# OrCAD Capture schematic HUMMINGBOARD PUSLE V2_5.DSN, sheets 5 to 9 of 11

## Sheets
5 13 HDMI: size B; title: HDMI
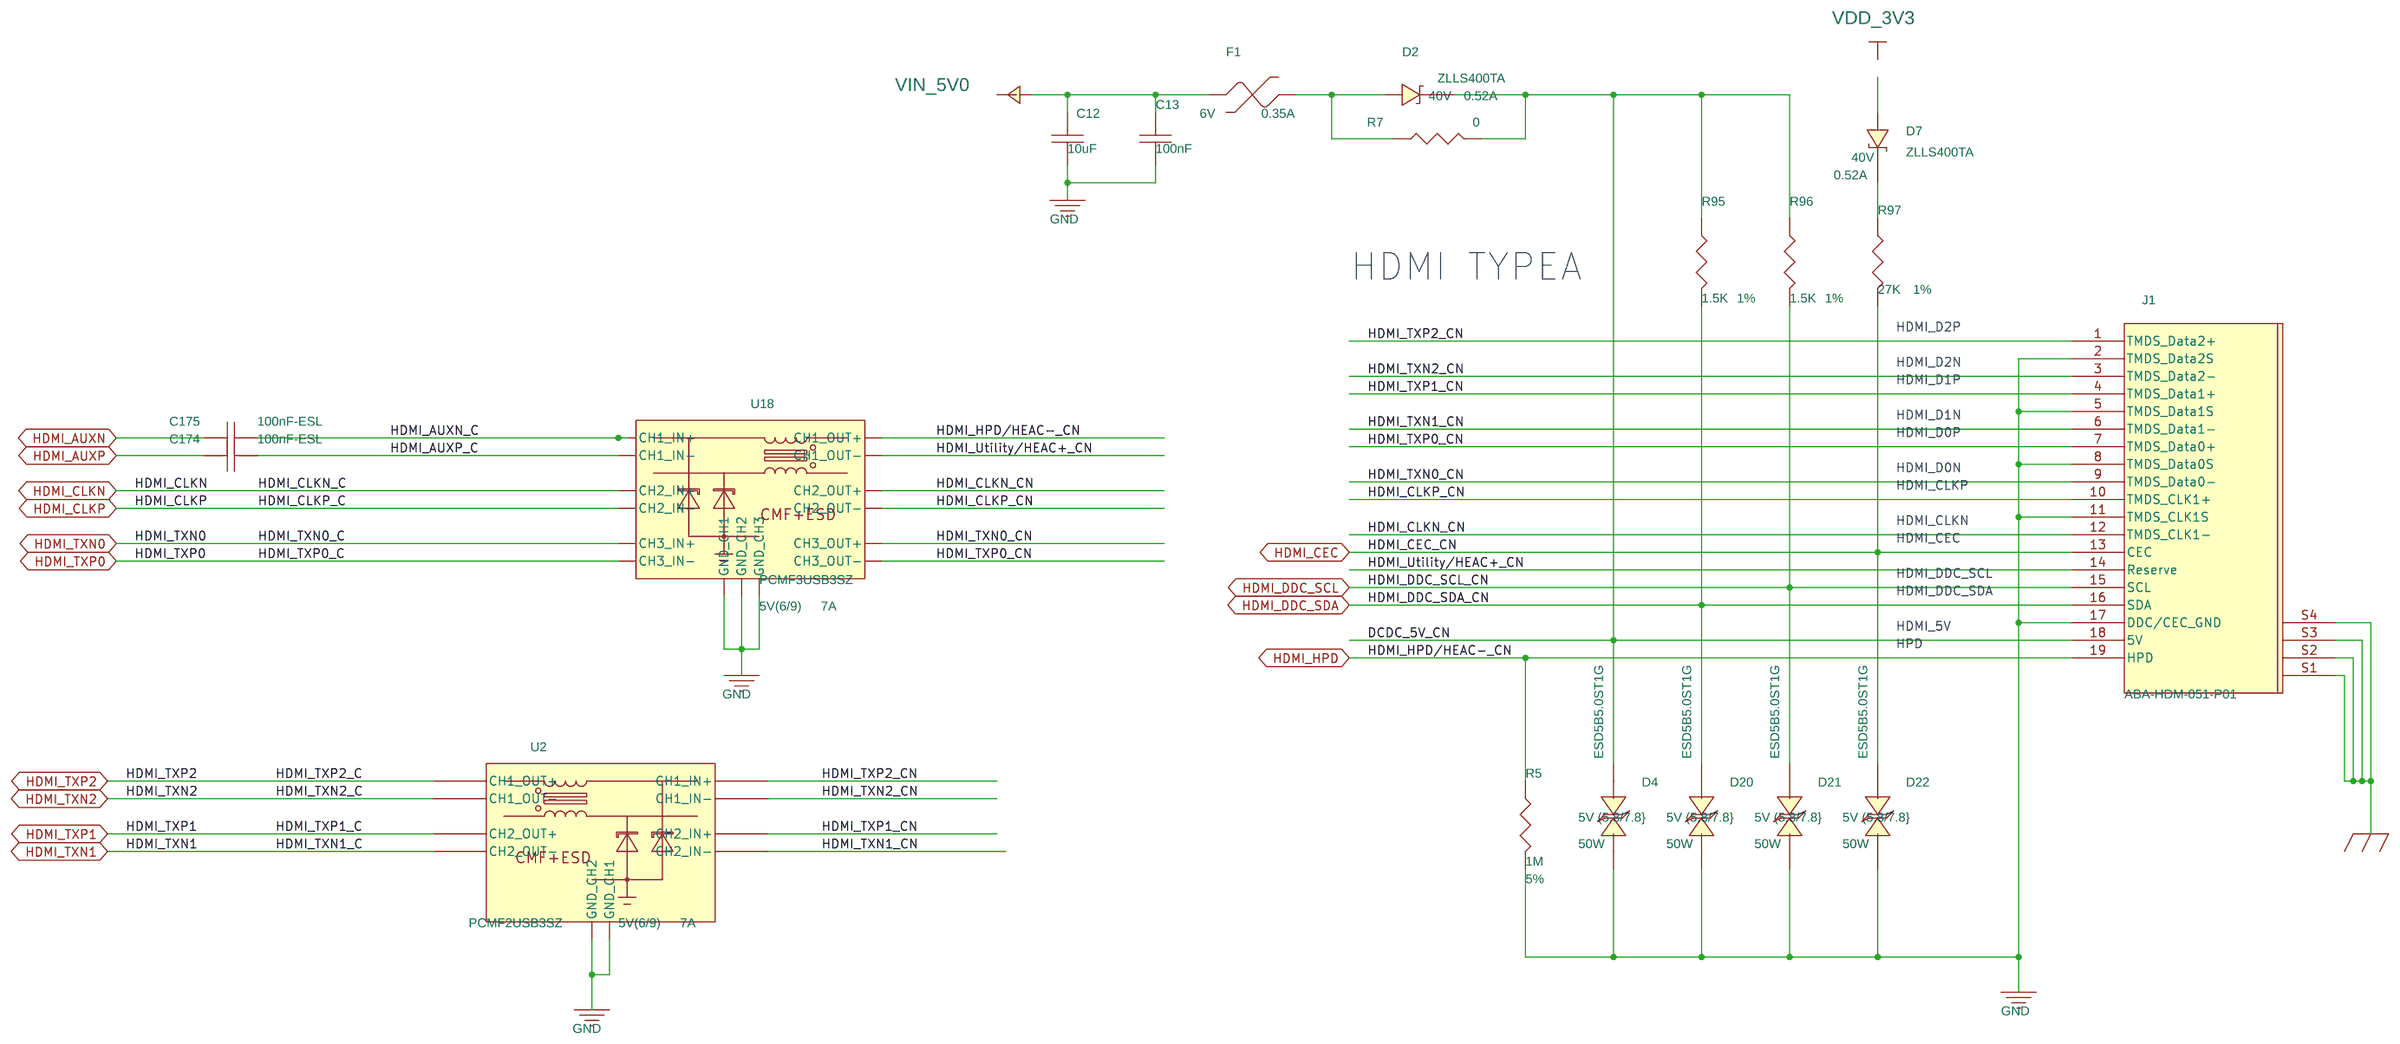
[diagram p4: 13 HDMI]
6 CODEC: size C; title: AUDIO
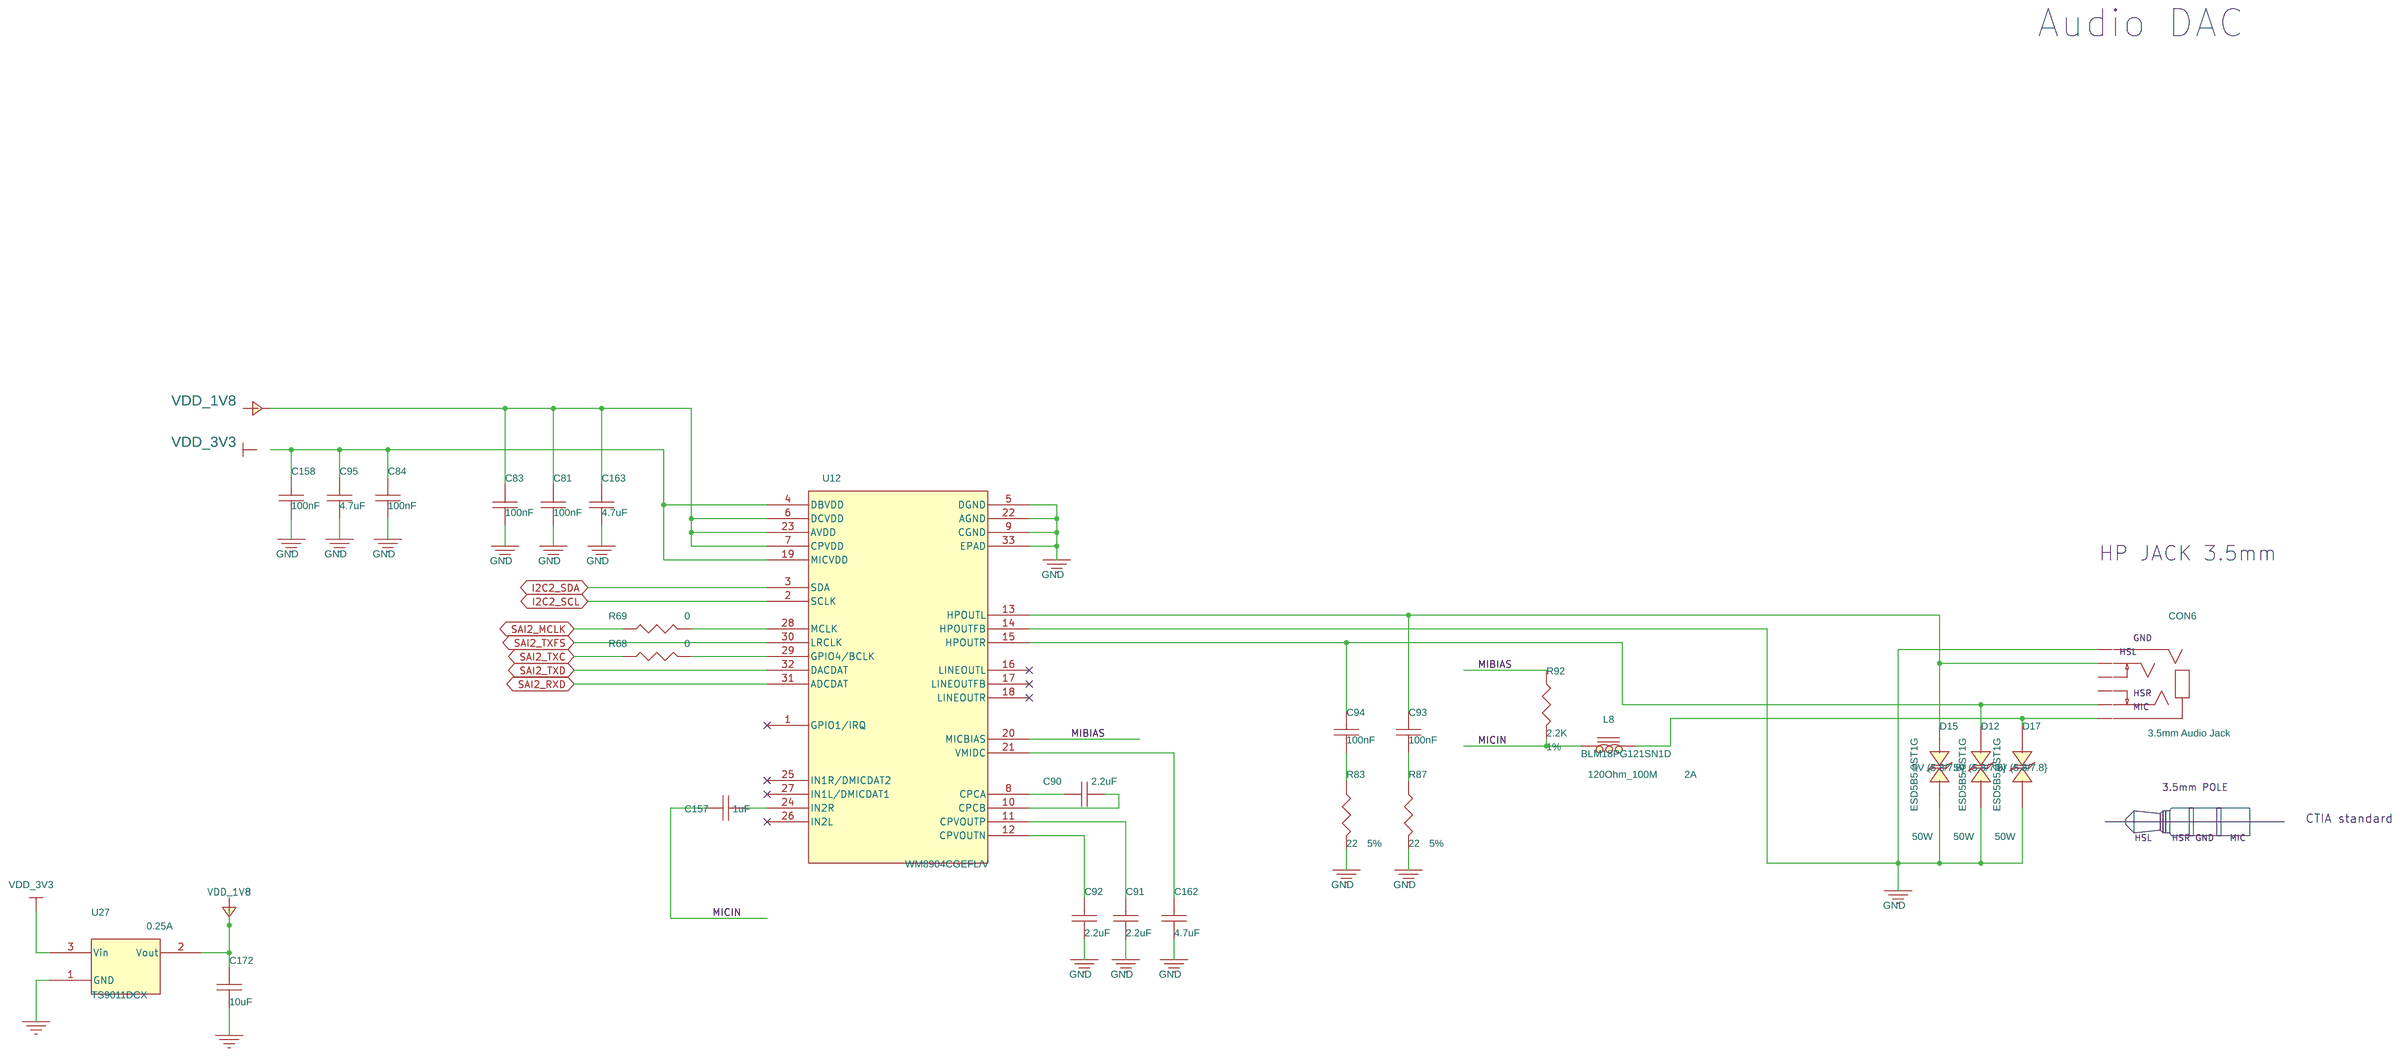
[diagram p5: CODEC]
7 Ethernet: size C; title: ETHERNET; rev: 2.4.0
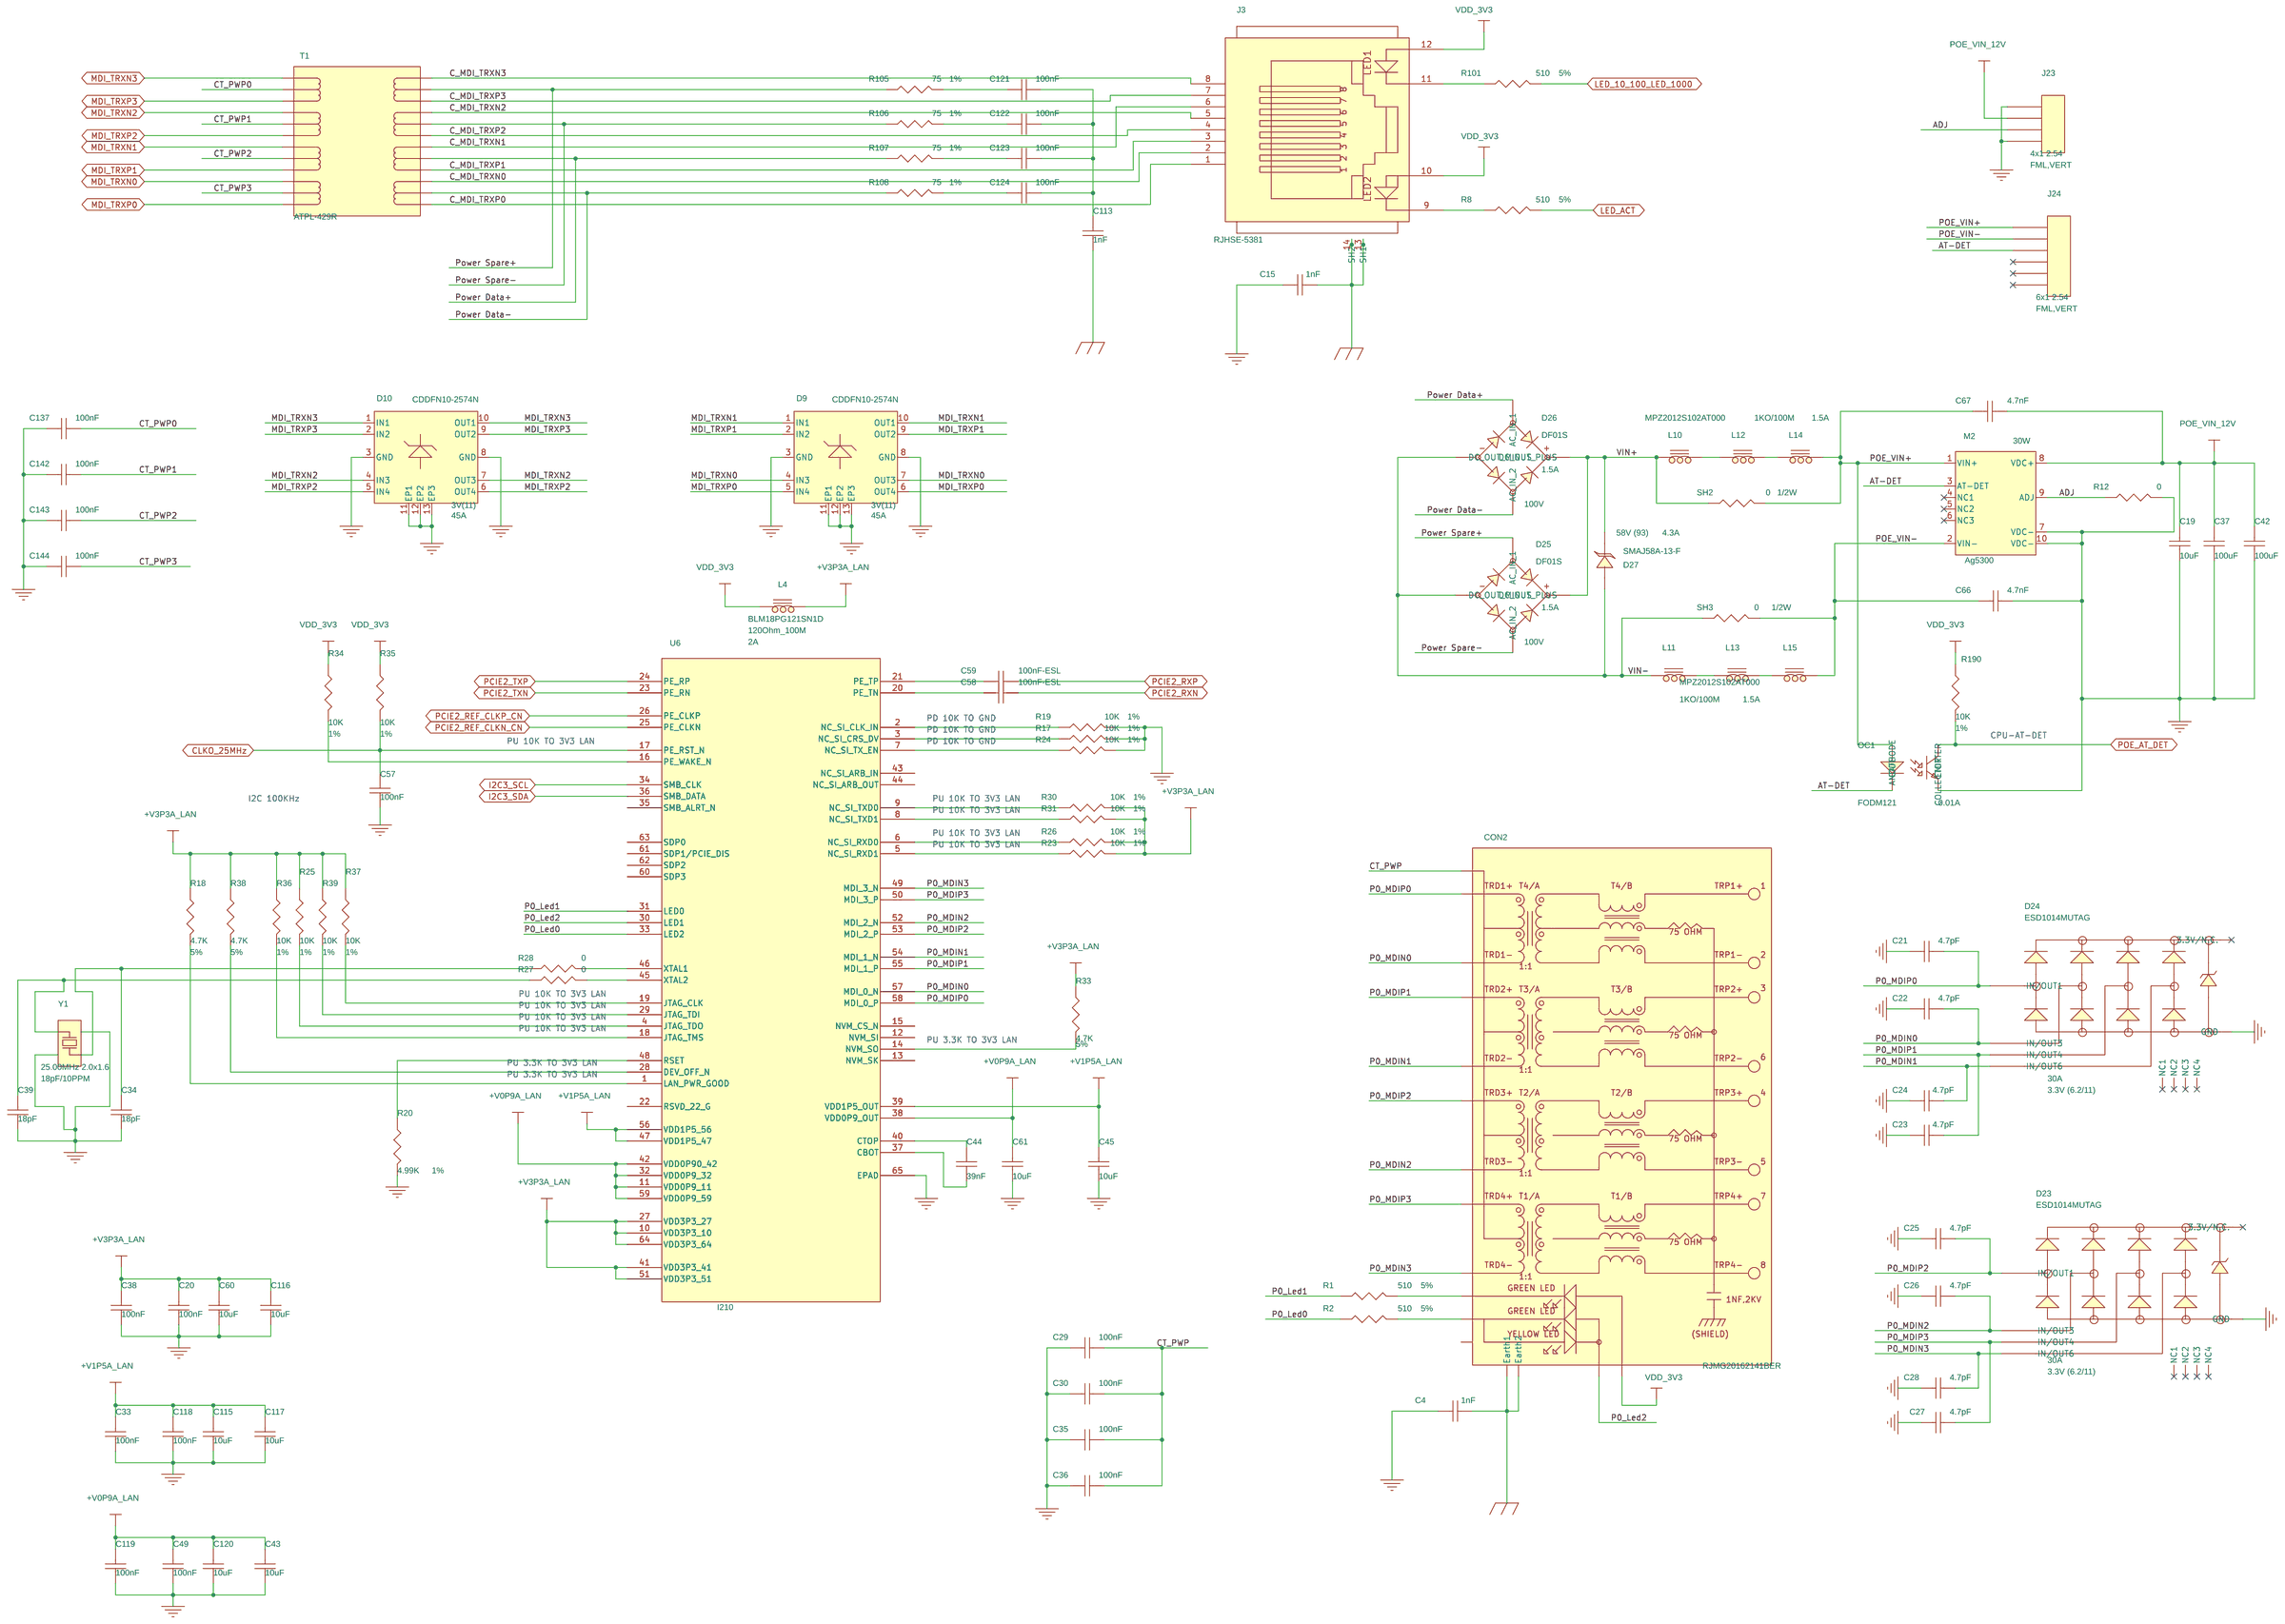
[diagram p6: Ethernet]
8 B-t-B Connectors: size C; title: B-T-B CONNECTORS; rev: 2.4.0
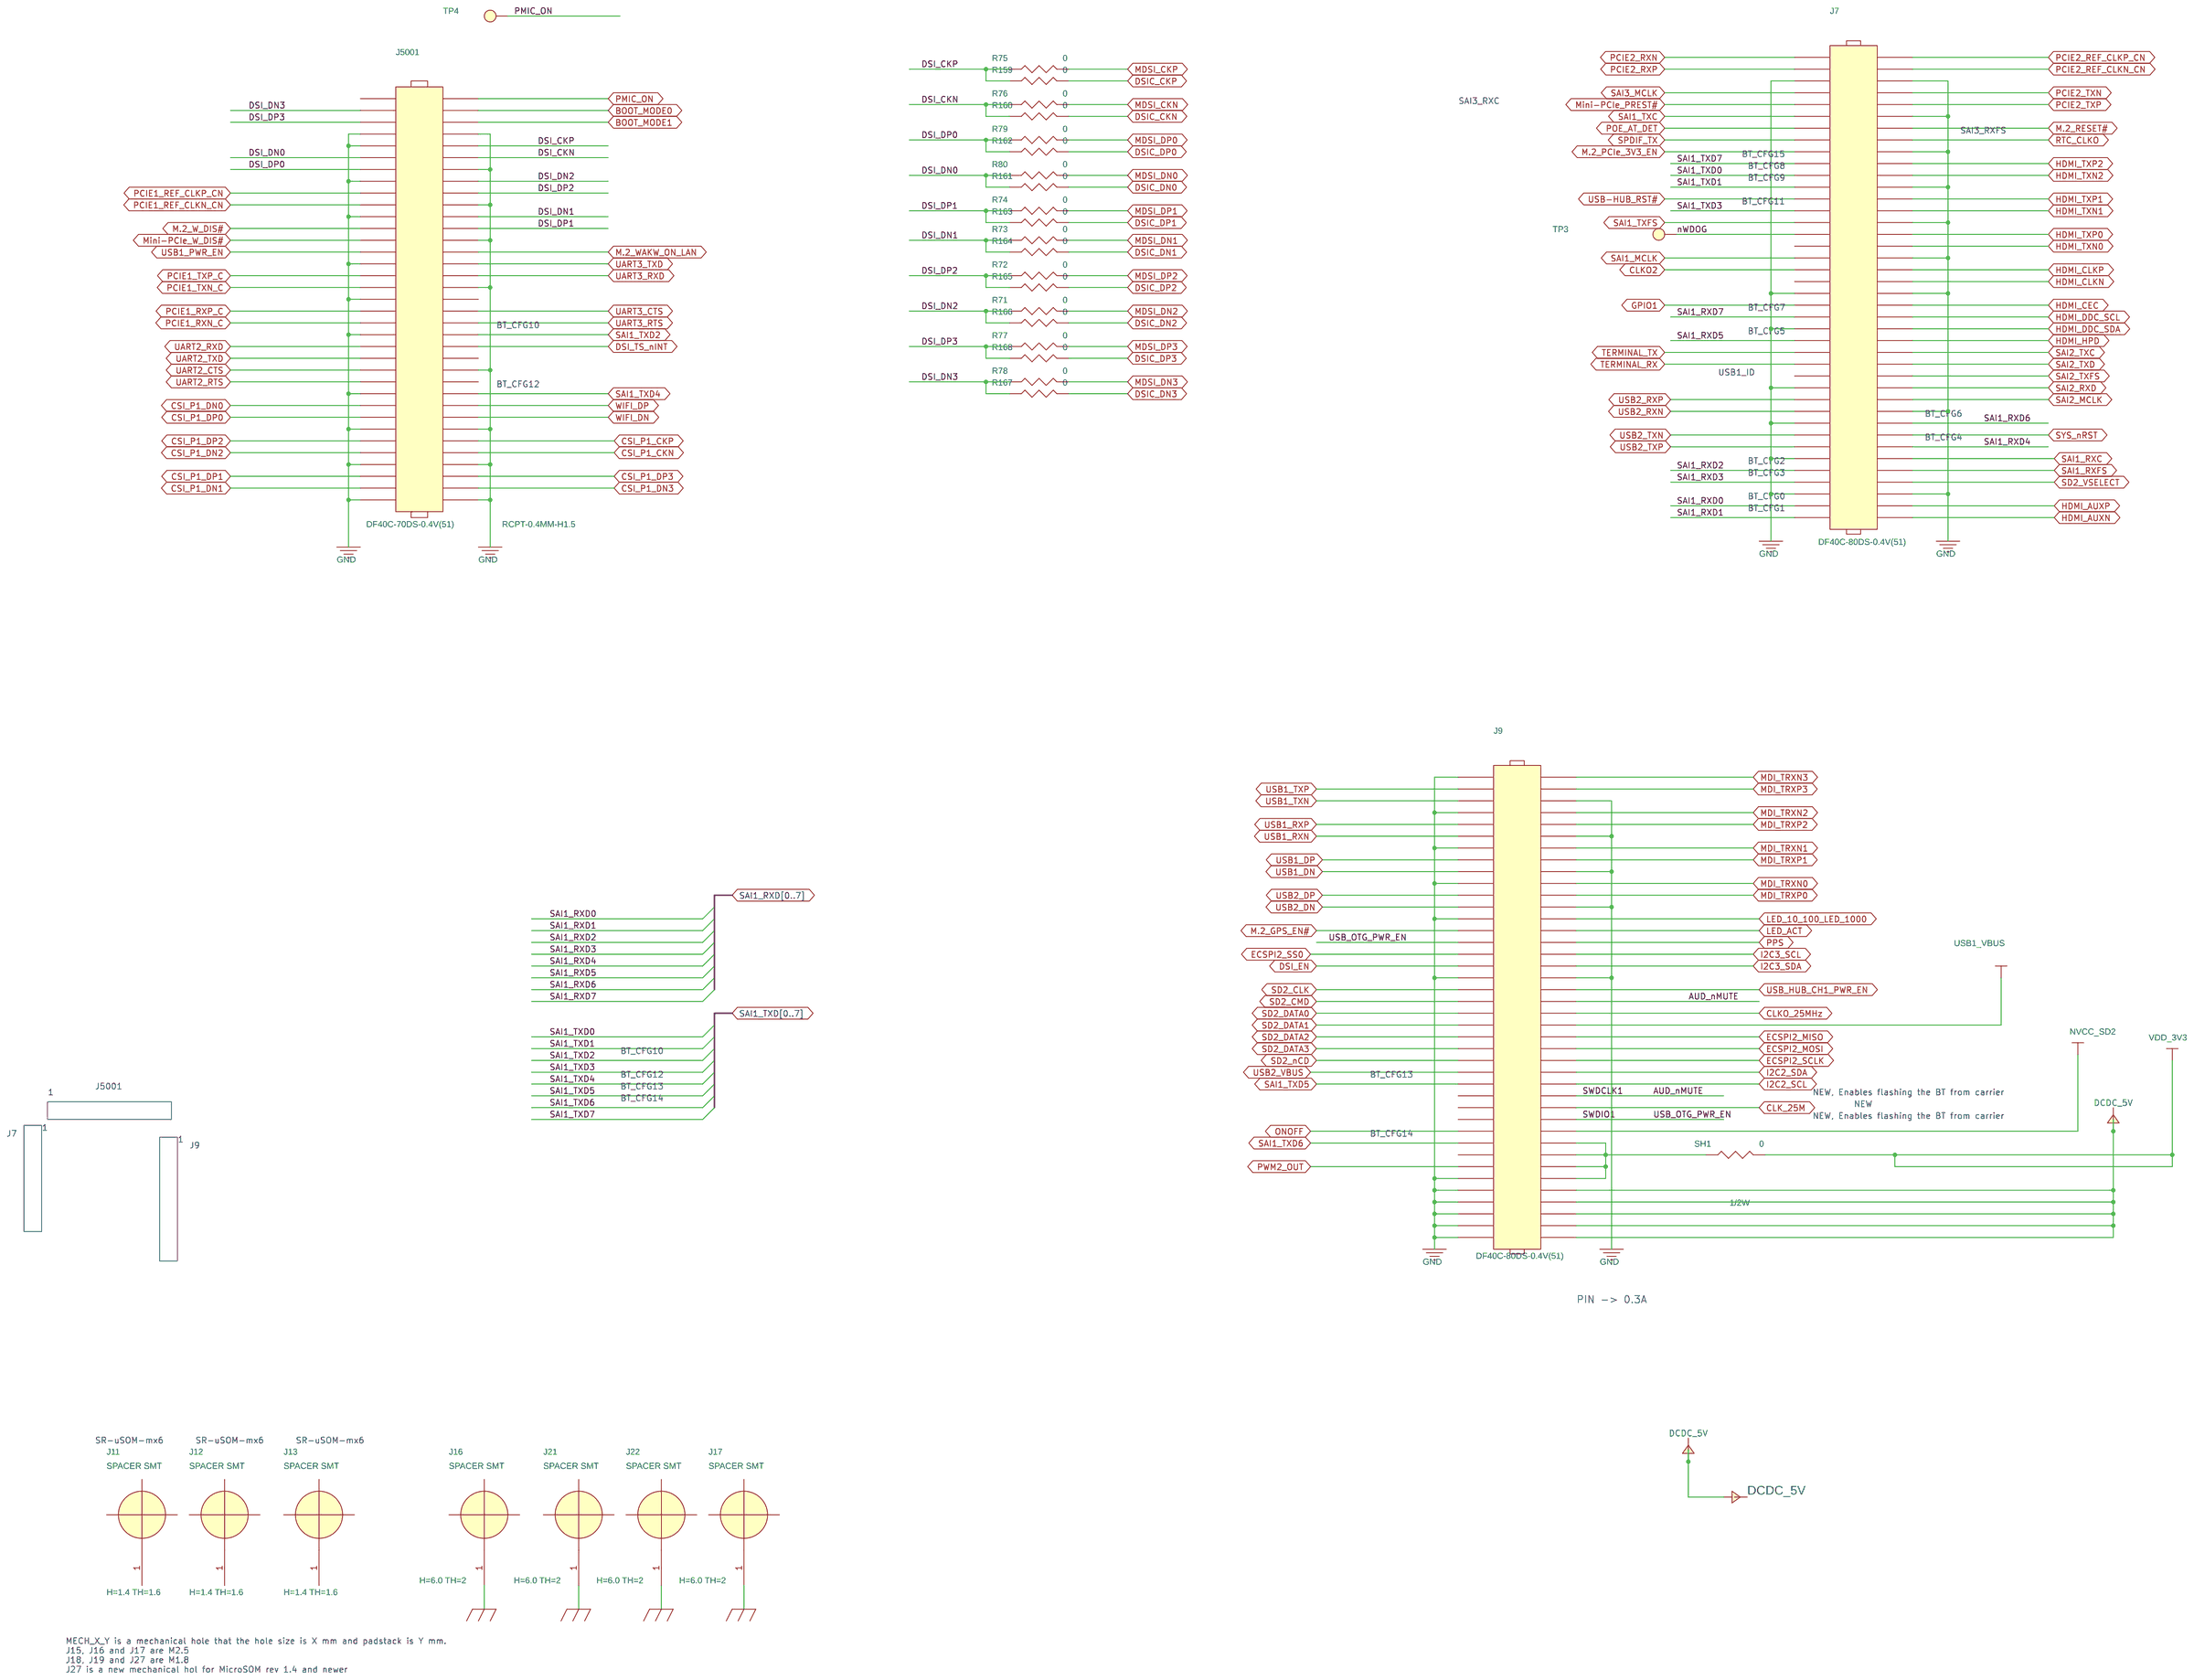
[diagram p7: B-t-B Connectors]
9 EXP CN: size C; title: BOOT, EXP; rev: 2.4.0
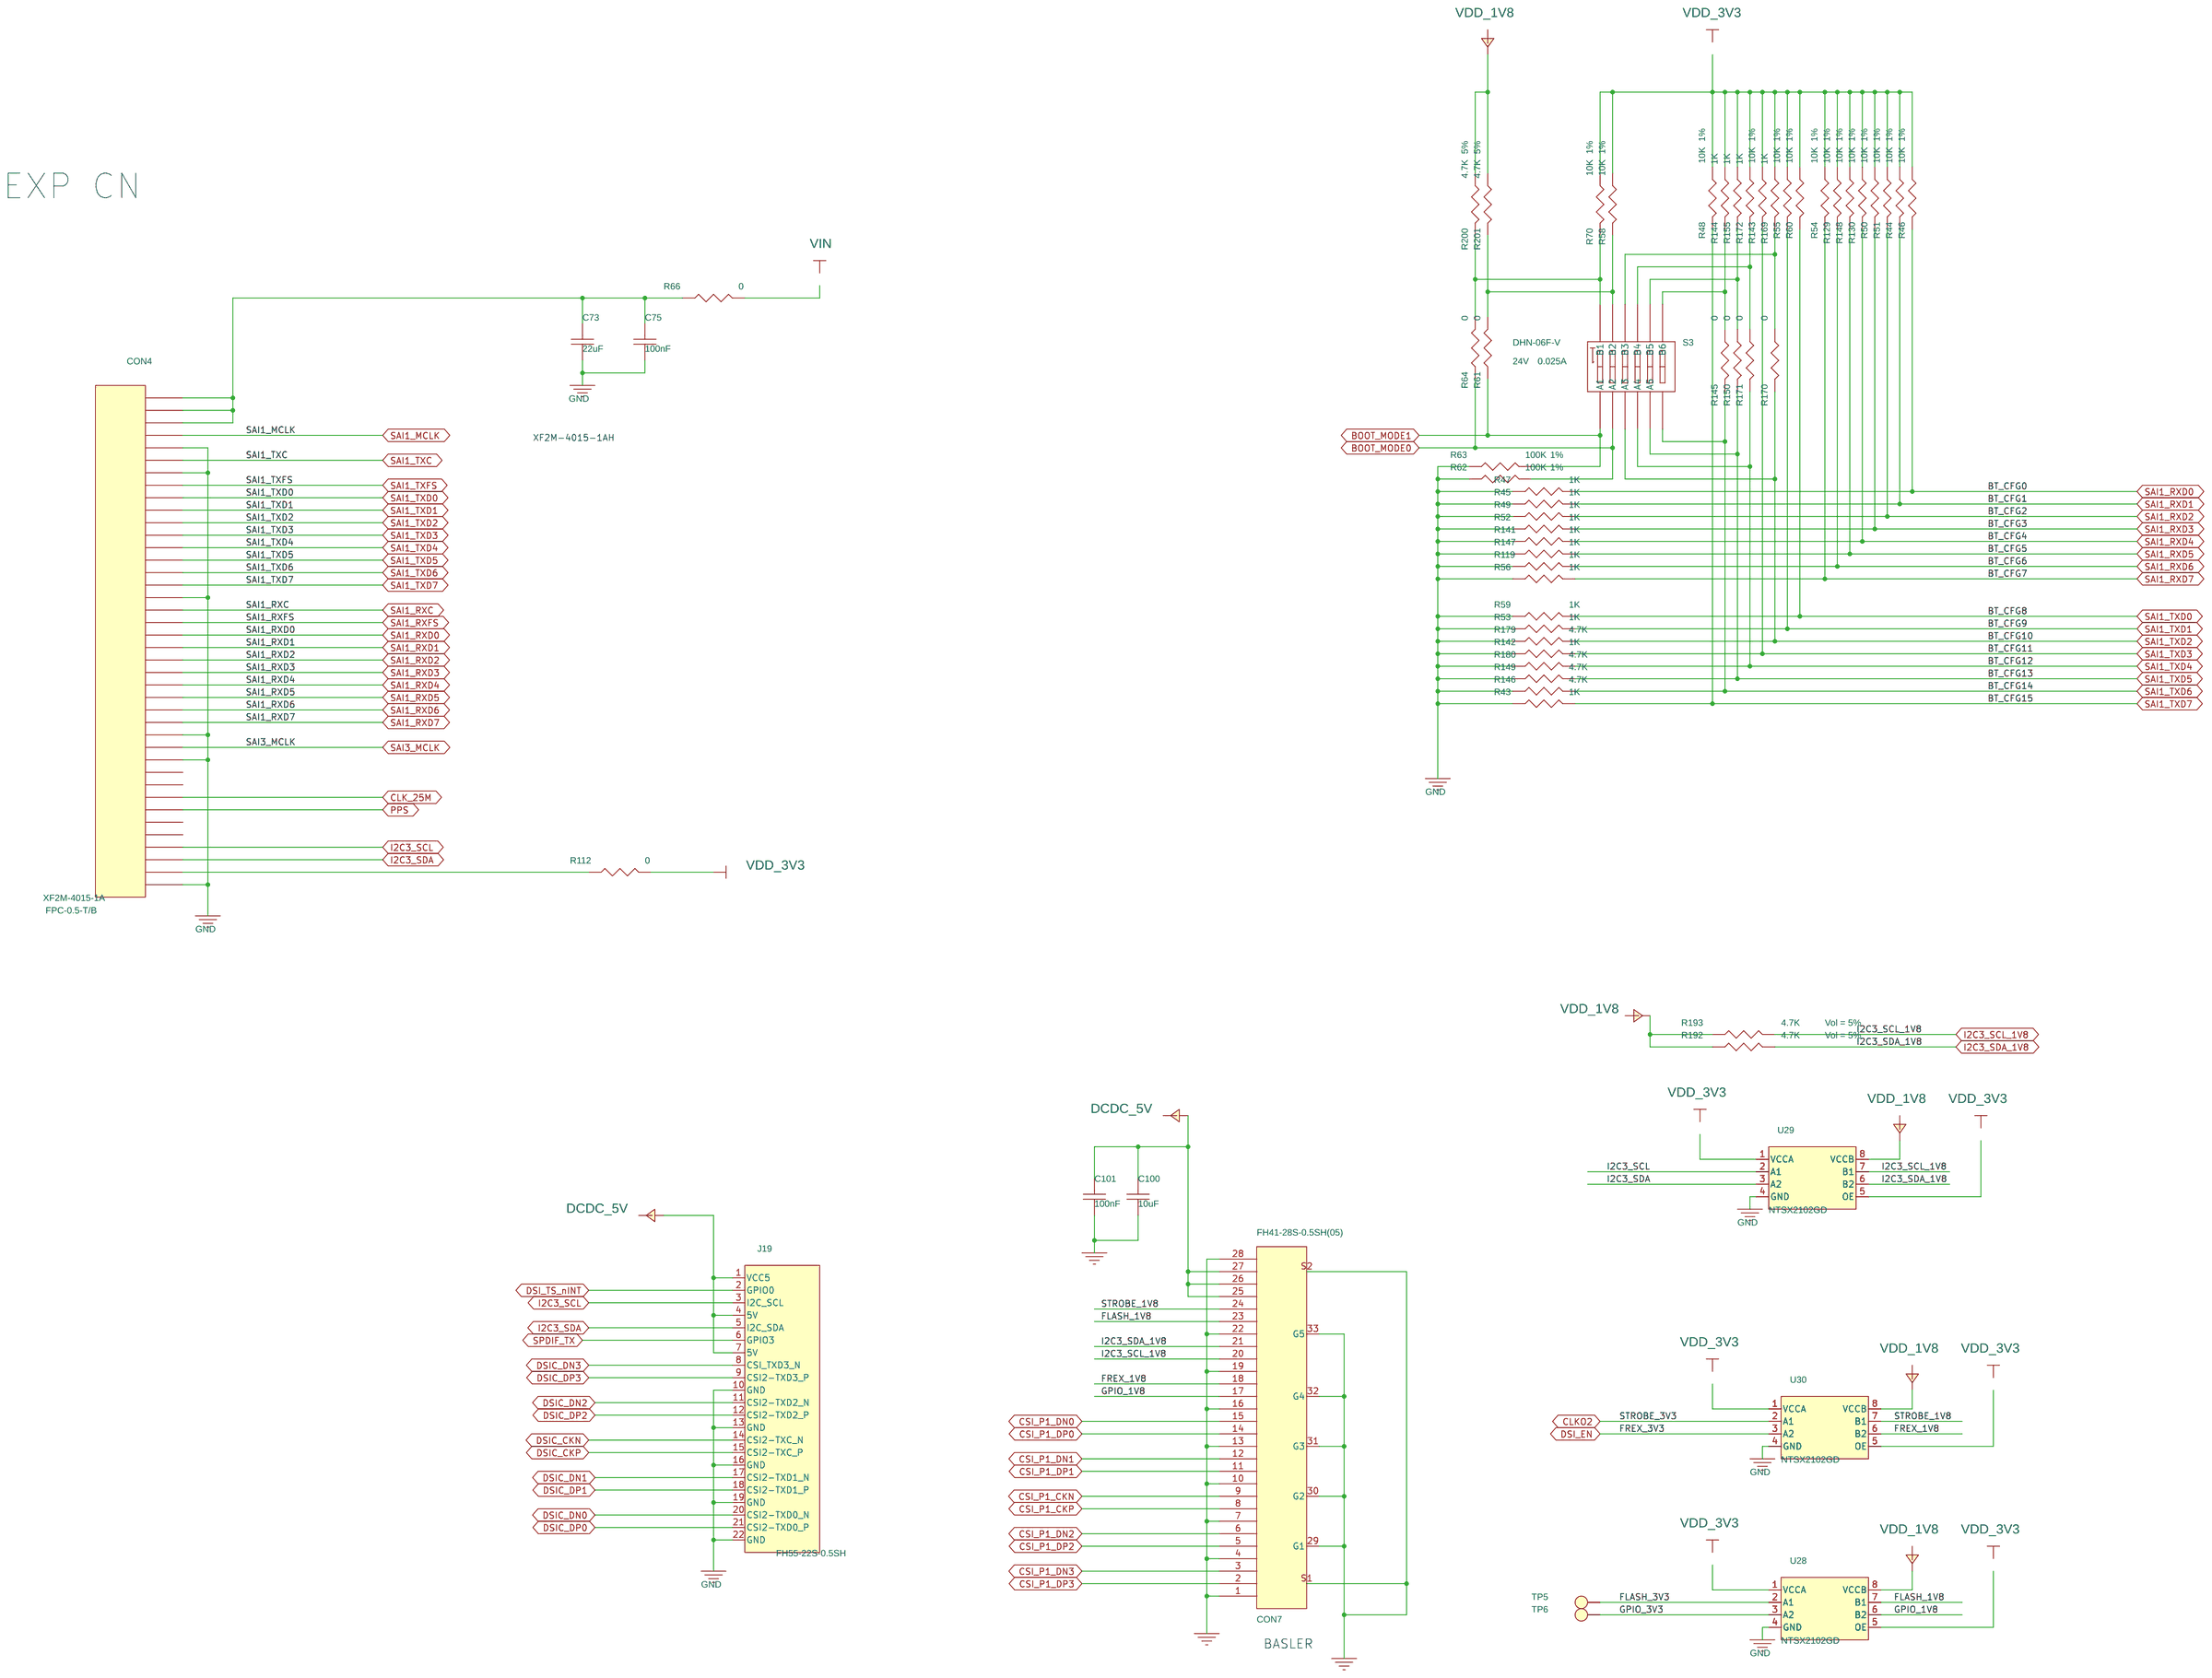
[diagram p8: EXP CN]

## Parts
sheet 13 HDMI
C12  10uF  [C0603]
C13  100nF  [C0402]
C174  100nF-ESL  [C0402]
C175  100nF-ESL  [C0402]
D2  ZLLS400TA  [ZLLS400TA]
D4  ESD5B5.0ST1G  [ESD5B5.0ST1G]
D7  ZLLS400TA  [ZLLS400TA]
D20  ESD5B5.0ST1G  [ESD5B5.0ST1G]
D21  ESD5B5.0ST1G  [ESD5B5.0ST1G]
D22  ESD5B5.0ST1G  [ESD5B5.0ST1G]
F1  6V  [PICOSMDC035S-2]
J1  ABA-HDM-051-P01  [ABA-HDM-051-P01]
R5  1M  [R0402]
R7  0  [R0402]
R95  1.5K  [R0402]
R96  1.5K  [R0402]
R97  27K  [R0402]
U2  PCMF2USB3SZ  [PCMF2USB3SZ]
U18  PCMF3USB3SZ  [PCMF3USB3SZ]
sheet B-t-B Connectors
J7  DF40C-80DS-0.4V(51)  [DF40C-80DS-0.4V(51)]
J9  DF40C-80DS-0.4V(51)  [DF40C-80DS-0.4V(51)]
J11  SPACER SMT
J12  SPACER SMT
J13  SPACER SMT
J16  SPACER SMT
J17  SPACER SMT
J21  SPACER SMT
J22  SPACER SMT
J5001  DF40C-70DS-0.4V(51)  [DF40C-70DS-0.4V(51)]
R71  0  [R0402]
R72  0  [R0402]
R73  0  [R0402]
R74  0  [R0402]
R75  0  [R0402]
R76  0  [R0402]
R77  0  [R0402]
R78  0  [R0402]
R79  0  [R0402]
R80  0  [R0402]
R159  0  [R0402]
R160  0  [R0402]
R161  0  [R0402]
R162  0  [R0402]
R163  0  [R0402]
R164  0  [R0402]
R165  0  [R0402]
R166  0  [R0402]
R167  0  [R0402]
R168  0  [R0402]
SH1  0  [R0603]
TP3  R 35
TP4  R 35
sheet CODEC
C81  100nF  [C0402]
C83  100nF  [C0402]
C84  100nF  [C0402]
C90  2.2uF  [C0402]
C91  2.2uF  [C0402]
C92  2.2uF  [C0402]
C93  100nF  [C0402]
C94  100nF  [C0402]
C95  4.7uF  [C0603]
C157  1uF  [C0402]
C158  100nF  [C0402]
C162  4.7uF  [C0603]
C163  4.7uF  [C0603]
C172  10uF  [C0603]
CON6  3.5mm Audio Jack  [PJ-3956-S124]
D12  ESD5B5.0ST1G  [ESD5B5.0ST1G]
D15  ESD5B5.0ST1G  [ESD5B5.0ST1G]
D17  ESD5B5.0ST1G  [ESD5B5.0ST1G]
L8  BLM18PG121SN1D  [BLM18PG121SN1D]
R68  0  [R0402]
R69  0  [R0402]
R83  22  [R0402]
R87  22  [R0402]
R92  2.2K  [R0402]
U12  WM8904CGEFL/V  [WM8904CGEFL/V]
U27  TS9011DCX  [TS9011DCX]
sheet Ethernet
C4  1nF  [C1206]
C15  1nF  [C1206]
C19  10uF  [C0805]
C20  100nF  [C0402]
C21  4.7pF  [C0402]
C22  4.7pF  [C0402]
C23  4.7pF  [C0402]
C24  4.7pF  [C0402]
C25  4.7pF  [C0402]
C26  4.7pF  [C0402]
C27  4.7pF  [C0402]
C28  4.7pF  [C0402]
C29  100nF  [C0402]
C30  100nF  [C0402]
C33  100nF  [C0402]
C34  18pF  [C0402]
C35  100nF  [C0402]
C36  100nF  [C0402]
C37  100uF  [C1210]
C38  100nF  [C0402]
C39  18pF  [C0402]
C42  100uF  [C1210]
C43  10uF  [C0603]
C44  39nF  [C0402]
C45  10uF  [C0603]
C49  100nF  [C0402]
C57  100nF  [C0402]
C58  100nF-ESL  [C0402]
C59  100nF-ESL  [C0402]
C60  10uF  [C0603]
C61  10uF  [C0603]
C66  4.7nF  [C1210]
C67  4.7nF  [C1210]
C113  1nF  [C1206]
C115  10uF  [C0603]
C116  10uF  [C0603]
C117  10uF  [C0603]
C118  100nF  [C0402]
C119  100nF  [C0402]
C120  10uF  [C0603]
C121  100nF  [C0402]
C122  100nF  [C0402]
C123  100nF  [C0402]
C124  100nF  [C0402]
C137  100nF  [C0402]
C142  100nF  [C0402]
C143  100nF  [C0402]
C144  100nF  [C0402]
CON2  RJMG20162141BER  [RJMG20162141BER]
D9  CDDFN10-2574N  [CDDFN10-2574N]
D10  CDDFN10-2574N  [CDDFN10-2574N]
D23  ESD1014MUTAG  [ESD1014MUTAG]
D24  ESD1014MUTAG  [ESD1014MUTAG]
D25  DF01S  [DF01S]
D26  DF01S  [DF01S]
D27  SMAJ58A-13-F  [SMAJ58A-13-F]
J3  RJHSE-5381  [RJHSE-5381]
J23  4x1 2.54  [SLW-104-01-G-S]
J24  6x1 2.54  [SLW-106-01-G-S]
L4  BLM18PG121SN1D  [BLM18PG121SN1D]
L10  MPZ2012S102AT000  [MPZ2012S102AT000]
L11  MPZ2012S102AT000  [MPZ2012S102AT000]
L12  MPZ2012S102AT000  [MPZ2012S102AT000]
L13  MPZ2012S102AT000  [MPZ2012S102AT000]
L14  MPZ2012S102AT000  [MPZ2012S102AT000]
L15  MPZ2012S102AT000  [MPZ2012S102AT000]
M2  Ag5300  [Ag5300]
OC1  FODM121  [FODM121]
R1  510  [R0402]
R2  510  [R0402]
R8  510  [R0402]
R12  0  [R0402]
R17  10K  [R0402]
R18  4.7K  [R0402]
R19  10K  [R0402]
R20  4.99K  [R0402]
R23  10K  [R0402]
R24  10K  [R0402]
R25  10K  [R0402]
R26  10K  [R0402]
R27  0  [R0402]
R28  0  [R0402]
R30  10K  [R0402]
R31  10K  [R0402]
R33  4.7K  [R0402]
R34  10K  [R0402]
R35  10K  [R0402]
R36  10K  [R0402]
R37  10K  [R0402]
R38  4.7K  [R0402]
R39  10K  [R0402]
R101  510  [R0402]
R105  75  [R0402]
R106  75  [R0402]
R107  75  [R0402]
R108  75  [R0402]
R190  10K  [R0402]
SH2  0  [R0603]
SH3  0  [R0603]
T1  ATPL-429R  [ATPL-429R]
U6  I210  [I210]
Y1  25.00MHz 2.0x1.6  [Q22FA1280026501]
sheet EXP CN
C73  22uF  [C0805]
C75  100nF  [C0402]
C100  10uF  [C0603]
C101  100nF  [C0402]
CON4  XF2M-4015-1A  [XF2M-4015-1A]
CON7  FH41-28S-0.5SH(05)  [FH41-28S-0.5SH(05)]
J19  FH55-22S-0.5SH  [FH55-22S-0.5SH]
R43  1K  [R0402]
R44  10K  [R0402]
R45  1K  [R0402]
R46  10K  [R0402]
R47  1K  [R0402]
R48  10K  [R0402]
R49  1K  [R0402]
R50  10K  [R0402]
R51  10K  [R0402]
R52  1K  [R0402]
R53  1K  [R0402]
R54  10K  [R0402]
R55  10K  [R0402]
R56  1K  [R0402]
R58  10K  [R0402]
R59  1K  [R0402]
R60  10K  [R0402]
R61  0  [R0402]
R62  100K  [R0402]
R63  100K  [R0402]
R64  0  [R0402]
R66  0  [R0402]
R70  10K  [R0402]
R112  0  [R0402]
R119  1K  [R0402]
R129  10K  [R0402]
R130  10K  [R0402]
R141  1K  [R0402]
R142  1K  [R0402]
R143  10K  [R0402]
R144  1K  [R0402]
R145  0  [R0402]
R146  4.7K  [R0402]
R147  1K  [R0402]
R148  10K  [R0402]
R149  4.7K  [R0402]
R150  0  [R0402]
R155  1K  [R0402]
R169  1K  [R0402]
R170  0  [R0402]
R171  0  [R0402]
R172  1K  [R0402]
R179  4.7K  [R0402]
R180  4.7K  [R0402]
R192  4.7K  [R0402]
R193  4.7K  [R0402]
R200  4.7K  [R0402]
R201  4.7K  [R0402]
S3  DHN-06F-V  [DHN-06F-V]
TP5  R 35
TP6  R 35
U28  NTSX2102GD  [NTSX2102GD]
U29  NTSX2102GD  [NTSX2102GD]
U30  NTSX2102GD  [NTSX2102GD]

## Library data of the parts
C12 C43 C45 C60 C61 C115-C117 C120 = CAP_NP1: CAP CER 10uF ±10% 16V X5R 0603; Category : Capacitors (Size: 0603); Digikey P/N: 490-10728-2-ND; Manufacturer: Murata Electronics North America; Part Num#: GRM188R61C106KAALD; Rating: 16V; SolidRun P/N: CA30014; Vol: 10%
C13 C20 C33 C38 C49 C57 C81 C83 C84 C93 C94 C118 C119 C158 = CAP_NP1: CAP CER 0.1uF ±10% 16V X7R 0402; Category : Capacitors (Size: 0402); Digikey P/N: 1276-1001-1-ND; Manufacturer: Samsung Electro-Mechanics; Part Num#: CL05B104KO5NNNC; Rating: 16V; SolidRun P/N: CA20013; Vol: 10%
C58 C59 C174 C175 = CAP_NP1: CAP CER 0.1uF ±10% 25V X7R 0402; Category : Capacitors (Size: 0402); Manufacturer: CAPAX; Part Num#: 0402X104K250SNT; Rating: 25V; SolidRun P/N: CA20090; Vol: 10%
D2 D7 = Diode-STK: DIODE SCHOTTKY 40V 520MA SOD323; Category: DI-Diode; Digikey P/N: ZLLS400TATR-ND; Manufacturer: Diodes Incorporated; Rating: 0.52A; SolidRun P/N: DI00234; Vol: 40V; Datasheet: https://www.diodes.com/assets/Datasheets/ZLLS400.pdf
D4 D12 D15 D17 D20-D22 = TVS-BI: TVS DIODE 5VWM SOD523 BI; Category : DI-TVS; Digikey P/N: ESD5B5.0ST1GOSTR-ND; Manufacturer: ON Semiconductor; Rating: 50W; SolidRun P/N: DI00242; Vol: 5V (5.8/7.8}; Datasheet: http://www.onsemi.com/pub/Collateral/ESD5B5.0ST1-D.PDF
F1 = FUSE_RESETTABLE: PTC RESET FUSE 6V 350MA 0805; Category : Fuse-PTC; Digikey P/N: PICOSMDC035S-2TR-ND; Manufacturer: Littelfuse Inc.; Rating: 0.35A; SolidRun P/N: FS00020; Datasheet: http://www.littelfuse.com/~/media/electronics/product_specifications/resettable_ptcs/littelfuse_ptc_picosmdc035s_2_product_specification.pdf.pdf
J1 = J-HDMI_connector: HDMI Connector; Category : CON-HDMI/DP; Manufacturer: LOTES; SolidRun P/N: CO00006; VOL: HDMI Connector
R5 = RES1: RES SMD 1M OHM 5% 1/16W 0402; Category : Resistors (Size: 0402); Digikey P/N: 311-1.0MJRCT-ND; Manufacturer: YAGEO; Part Num#: RC0402JR-071ML; Rating: 1/16W; SolidRun P/N: RE20416; Vol: 5%
R7 R12 R27 R28 R61 R64 R68 R69 R145 R150 R170 R171 = RES1: RES SMD 0 OHM JUMPER 1/16W 0402; Category : Resistors (Size: 0402); Digikey P/N: 311-0.0JRCT-ND; Manufacturer: YAGEO; Part Num#: RC0402JR-070RL; Rating: 1/16W; SolidRun P/N: RE20009
R95 R96 = RES1: RES SMD 1.5K OHM 1% 1/16W 0402; Category : Resistors (Size: 0402); Manufacturer: THYE MING; Part Num#: CR-02FL6---1K5; Rating: 1/16W; SolidRun P/N: RE20029; Vol: 1%
R97 = RES1: RES SMD 27K OHM 1% 1/16W 0402; Category : Resistors (Size: 0402); Digikey P/N: 311-27.0KLRCT-ND; Manufacturer: YAGEO; Part Num#: RC0402FR-0727KL; Rating: 1/16W; SolidRun P/N: RE20495; Vol: 1%
U2 = D-PCMF2USB3S: CMC 4LN SMD ESD USB 3.1, USB 2.0, HDMI 2.0, HDMI 1.4; Category : DI-TVS; Digikey P/N: 1727-2509-2-ND; Manufacturer: Nexperia USA Inc.; Rating: 7A; SolidRun P/N: DI00240; Vol: 5V(6/9); Datasheet: https://assets.nexperia.com/documents/data-sheet/PCMFXUSB3S_SER.pdf
U18 = D-PCMF3USB3S: CMC 6LN SMD ESD USB 3.1, USB 2.0, HDMI 2.0, HDMI 1.4; Category : DI-TVS; Digikey P/N: 1727-2510-2-ND; Manufacturer: Nexperia USA Inc.; Rating: 7A; SolidRun P/N: DI00239; Vol: 5V(6/9); Datasheet: https://assets.nexperia.com/documents/data-sheet/PCMFXUSB3S_SER.pdf
J7 J9 = J-DF40C-80DS-0.4V(51): CONN RCPT 80POS 0.4MM SMD GOLD Without reinforcing metal fitting 1.5mm; Category : CON-HEADER; Digikey P/N: H11633TR-ND; Manufacturer: Hirose Electric Co Ltd; SolidRun P/N: CO00017; VOL: RCPT-0.4MM-H1.5; Datasheet: https://www.hirose.com/product/download/?distributor=digikey&type=2d&lang=en&num=DF40C-80DS-0.4V(51)
J11-J13 = SPACER_SMT: SPACER H=1.4MM  TH=1.6MM - Used as imx6-uSOM spacer; Category : MECH-SPACER; Manufacturer: A-Link; Part Num#: N0143416A; SolidRun P/N: MCH0007; Vol: H=1.4 TH=1.6; Datasheet: http://www.alink.com.tw/smt%20fastener%20standard%20parts.html
J16 J17 J21 J22 = SPACER_SMT: 6mm PCB spacer to enclsoure (used in HummingBoard); Category : MECH-SPACER; Digikey P/N: 732-7103-2-ND; Manufacturer: Wurth Elektronik; Part Num#: WE 977-406-024-3R; SolidRun P/N: MCH0009; Vol: H=6.0 TH=2; Datasheet: http://katalog.we-online.de/em/datasheet/9774060243R.pdf
J5001 = J-DF40C-70DS-0.4V(51): CONN RCPT 70POS 0.4MM SMD GOLD Without reinforcing metal fitting 1.5 mm; Category : CON-HEADER; Digikey P/N: H11631TR-ND; Manufacturer: Hirose Electric Co Ltd; SolidRun P/N: CO00511; VOL: RCPT-0.4MM-H1.5; Datasheet: https://www.hirose.com/product/download/?distributor=digikey&type=2d&lang=en&num=DF40C-70DS-0.4V(51)
R71-R80 R159-R168 = RES1: RES SMD 0 OHM JUMPER 1/16W 0402; Category: Resistors (Size: 0402); Category : Resistors (Size: 0402); Digikey P/N: 311-0.0JRCT-ND; Manufacturer: YAGEO; Part Num#: RC0402JR-070RL; Rating: 1/16W; SolidRun P/N: RE20009
SH1-SH3 = RES1: RES SMD 0 OHM JUMPER 1/2W 0603; Category : Resistors (Size: 0603); Digikey P/N: 36-5110CT-ND; Manufacturer: Keystone Electronics; Part Num#: 5110; Rating: 1/2W; SolidRun P/N: RE30017
TP3-TP6 = T_POINT_R: TEST POINT MINIATURE SMT; Category : Test Point
C90-C92 = CAP_NP1: CAP CER 2.2uF ±20% 10V X5R 0402; Category : Capacitors (Size: 0402); Digikey P/N: 399-7375-1-ND; Manufacturer: KEMET; Part Num#: C0402C225M8PACTU; Rating: 10V; SolidRun P/N: CA20805; Vol: 20%
C95 C162 C163 = CAP_NP1: CAP CER 4.7uF ±10% 6.3V X5R; Category : Capacitors (Size: 0603); Digikey P/N: 1276-1045-2-ND; Manufacturer: Samsung Electro-Mechanics; Part Num#: CL10A475KQ8NNNC; Rating: 6.3V; SolidRun P/N: CA30003; Vol: 10%
C157 = CAP_NP1: CAP CER 1UF 10V X5R 0402; Category : Capacitors (Size: 0402); Digikey P/N: 1276-1076-1-ND; Manufacturer: Samsung Electro-Mechanics; Part Num#: CL05A105KP5NNNC; Rating: 10V; SolidRun P/N: CA20005; Vol: 10%
C172 = CAP_NP1: CAP CER 10uF ±10% 6.3V X5R 0603; Category : Capacitors (Size: 0603); Digikey P/N: 1276-1038-1-ND; Manufacturer: Samsung Electro-Mechanics; Part Num#: CL10A106KQ8NNNC; Rating: 6.3V; SolidRun P/N: CA30001; Vol: 10%
CON6 = J-PJ-3956-S124-AUDIO: 3.5mm Audio Jack with Microphone input and switch left and right; Category : CON-AUDIO; Manufacturer: Contact Technology; SolidRun P/N: CO00637
L4 L8 = Ferrite_Bead: Bead 120ohm, 100MHz, 2A; Category : COILS-FERRIT; Digikey P/N: 490-1037-2-ND; Manufacturer: Murata Electronics North America; Rating: 2A; SolidRun P/N: IN00003; Vol: 120Ohm_100M; Datasheet: https://www.murata.com/en-us/products/productdata/8796738650142/ENFA0003.pdf
R83 R87 = RES1: RES SMD 22 OHM 5% 1/16W 0402; Category : Resistors (Size: 0402); Digikey P/N: 311-22JRCT-ND; Manufacturer: YAGEO; Part Num#: RC0402JR-0722RL; Rating: 1/16W; SolidRun P/N: RE20021; Vol: 5%
R92 = RES1: RES SMD 2.2K OHM 1% 1/16W 0402; Category : Resistors (Size: 0402); Digikey P/N: 311-2.20KLRCT-ND; Manufacturer: YAGEO; Part Num#: RC0402FR-072K2L; Rating: 1/16W; SolidRun P/N: RE20204; Vol: 1%
U12 = IC-WM8904: IC CODEC STEREO ULP 32QFN; Category : IC-AUDIO; Digikey P/N: WM8904CGEFL/V-ND; Manufacturer: Cirrus Logic Inc; SolidRun P/N: IC01220; Datasheet: https://d3uzseaevmutz1.cloudfront.net/pubs/proDatasheet/WM8904_Rev4.0.pdf
U27 = IC-TS9011DCX: LDO - 1.8V output, 0.25A, 12V maximum in; Category : IC-PWR-LDO; Digikey P/N: TS9011DCXRFG-ND; Manufacturer: Taiwan Semiconductor Corporation; Rating: 0.25A; SolidRun P/N: IC00014; VOL: 1.8V; Datasheet: http://www.taiwansemi.com/products/datasheet/TS9011_H1608.pdf
C4 C15 C113 = CAP_NP1: CAP CER 1nF ±10% 1KV X7R 1206; Category : Capacitors (Size: 1206); Digikey P/N: 490-3494-2-ND; Manufacturer: Murata Electronics North America; Part Num#: GRM31BR73A102KW01L; Rating: 1KV; SolidRun P/N: CA50002; Vol: 10%
C19 = CAP_NP1: CAP CER 10uF ±10% 25V X5R 0805; Category : Capacitors (Size: 0805); Digikey P/N: 490-5523-1-ND; Manufacturer: Murata Electronics North America; Part Num#: GRM21BR61E106KA73L; Rating: 25V; SolidRun P/N: CA40005; Vol: 10%
C21-C28 = CAP_NP1: CAP CER 4.7pF ±0.05pF 50V C0G/NP0 0402; Category : Capacitors (Size: 0402); Digikey P/N: 311-1033-1-ND; Manufacturer: Murata Electronics North America; Part Num#: GJM1555C1H4R7WB01D; Rating: 50V; SolidRun P/N: CA20807; Vol: 1%
C29 C30 C35 C36 C121-C124 C137 C142-C144 = CAP_NP1: CAP CER 0.1uF ±10% 50V X7R 0402; Category : Capacitors (Size: 0402); Digikey P/N: 490-10700-1-ND; Manufacturer: Murata Electronics North America; Part Num#: GRM155R71H104KE14D; Rating: 50V; SolidRun P/N: CA20147; Vol: 10%
C34 C39 = CAP_NP1: CAP CER 18pF ±1% 50V C0G/NPO 0402; Category : Capacitors (Size: 0402); Digikey P/N: 311-1643-1-ND; Manufacturer: YAGEO; Part Num#: CC0402FRNPO9BN180; Rating: 50V; SolidRun P/N: CA20017; Vol: 1%
C37 C42 = CAP_NP1: CAP CER 100uF ±20% 16V X5R 1210; Category : Capacitors (Size: 1210); Digikey P/N: 311-2052-1-ND; Manufacturer: YAGEO; Part Num#: CC1210MKX5R7BB107; Rating: 16V; SolidRun P/N: CA60008; Vol: 20%
C44 = CAP_NP1: CAP CER 39nF ±10% 10V X5R 0402; Category : Capacitors (Size: 0402); Digikey P/N: 490-8252-1-ND; Manufacturer: Murata Electronics North America; Part Num#: GRM155R61A393KA01D; Rating: 10V; SolidRun P/N: CA20804; Vol: 10%
C66 C67 = CAP_NP1: CAP CER 4.7nF ±10% 2000V X7R 1210 .High Voltage; Category : Capacitors (Size: 1210); Digikey P/N: 399-7104-1-ND; Manufacturer: KEMET; Part Num#: C1210C472KGRACTU; Rating: 2KV; SolidRun P/N: CA60009; Vol: 10%
CON2 = J-RJMG20162141BER-FCI: CONN MAGJACK 1PORT 1000 BASE-T; Category : CON-ETH/RJ; Digikey P/N: RJMG20162141BER-ND; Manufacturer: Amphenol Commercial Products; SolidRun P/N: CO00673; VOL: MAGJACK; Datasheet: https://www.amphenolcanada.com/ProductSearch/Drawings/AC/RJMG20162141BER.PDF
D9 D10 = D-CDDFN10-2574N: TVS Diode Array, 4 Channel, Ipp=45A, Vclump=11V, 1.7pF@1MHz, 10-DFN (3x2), -55°C ~ 85°C (TA); Category: DI-TVS; Digikey P/N: CDDFN10-2574NCT-ND; Manufacturer: Bourns Inc.; Rating: 45A; SolidRun P/N: DI00271; Vol: 3V(11); Datasheet: https://www.bourns.com/docs/product-datasheets/cddfn10-2574n.pdf
D23 D24 = D-ESD1014: TVS DIODE 3.3VWM 11VC 10UDFN; Category : DI-TVS; Digikey P/N: ESD1014MUTAGOSTR-ND; Manufacturer: ON Semiconductor; Rating: 30A; SolidRun P/N: DI00238; Vol: 3.3V (6.2/11); Datasheet: http://www.onsemi.com/pub/Collateral/ESD1014-D.PDF
D25 D26 = D-DF01S-Bridge: IC RECT BRIDGE 100V 1.5A 4-SMD; Category : DI-Diode; Digikey P/N: DF01STR-ND; Manufacturer: ON Semiconductor; Rating: 1.5A; SolidRun P/N: DI00235; Vol: 100V; Datasheet: https://www.fairchildsemi.com/datasheets/DF/DF005S.pdf
D27 = TVS-UNI-OLD: TVS DIODE 58VWM 93.6VC SMA; Category : DI-TVS; Digikey P/N: SMAJ58A-13-FDITR-ND; Manufacturer: Diodes Incorporated; Rating: 4.3A; SolidRun P/N: DI00244; Vol: 58V (93); Datasheet: https://www.diodes.com/assets/Datasheets/ds19005.pdf
J3 = J-RJHSE538x: CONN MOD JACK 8P8C R/A SHIELDED; Category : CON-ETH/RJ; Digikey P/N: RJHSE-5381-ND; Manufacturer: Amphenol Commercial Products; SolidRun P/N: CO00654; VOL: JACK 8P8C R/A SHIELDED; Datasheet: https://www.amphenolcanada.com/ProductSearch/drawings/AC/RJHSE538X.pdf
J23 = J-HEADER-4x1: 4 Position Receptacle Connector  Through Hole; Digikey P/N: SAM1089-04-ND; Manufacturer: Samtec Inc.; SolidRun P/N: CO00780; Vol: FML,VERT; Datasheet: http://suddendocs.samtec.com/catalog_english/slw.pdf
J24 = J-HEADER-6x1: 6 Position Receptacle Connector  Through Hole; Digikey P/N: SAM1089-06-ND; Manufacturer: Samtec Inc.; SolidRun P/N: CO00781; Vol: FML,VERT; Datasheet: http://suddendocs.samtec.com/prints/slw-s.pdf
L10-L15 = Ferrite_Bead: 1 kOhms @ 100MHz 1 Power Line Ferrite Bead 0805 (2012 Metric) 1.5A 150mOhm; Category: COILS-FERRIT; Category : COILS-FERRIT; Digikey P/N: 445-5223-2-ND; Manufacturer: TDK Corporation; Rating: 1.5A; SolidRun P/N: IN00128; Vol: 1KO/100M; Datasheet: https://product.tdk.com/info/en/catalog/datasheets/beads_commercial_power_mpz2012_en.pdf
M2 = M-AG5300-POE: Module POE PD, IEEE802.3at, 30W, Vout=12V, 57x14mm; Category: IC-ETH-POE; Manufacturer: Silvertel; Rating: 30W; SolidRun P/N: IC01301; VOL: 802.3af/at PD; Datasheet: http://silvertel.com/images/datasheets/Ag5300-datasheet-smallest-30W-Power-Over-Ethernet-Plus-Module-PoEplusPD.pdf
OC1 = OPTC-DC-4P: Optoisolator Transistor Output 3750Vrms 1 Channel 4-Mini-Flat; Category: IC-INT-OPT; Digikey P/N: FODM121-ND; Manufacturer: ON Semiconductor; Rating: 0.01A; SolidRun P/N: IC01209; VOL: 1.4V; Datasheet: https://www.fairchildsemi.com/datasheets/FO/FODM121.pdf
R1 R2 R8 R101 = RES1: RES SMD 510 OHM 5% 1/16W 0402; Category : Resistors (Size: 0402); Digikey P/N: 311-510JRCT-ND; Manufacturer: YAGEO; Part Num#: RC0402JR-07510RL; Rating: 1/16W; SolidRun P/N: RE20022; Vol: 5%
R17 R19 R23-R26 R30 R31 R34-R37 R39 R44 R46 R48 R50 R51 R54 R55 R58 R60 R70 R129 R130 R143 R148 R190 = RES1: RES SMD 10K OHM 1% 1/16W 0402; Category : Resistors (Size: 0402); Digikey P/N: 311-10.0KLRCT-ND; Manufacturer: YAGEO; Part Num#: RC0402FR-0710KL; Rating: 1/16W; SolidRun P/N: RE20013; Vol: 1%
R18 R33 R38 R146 R149 R179 R180 R200 R201 = RES1: RES SMD 4.7K OHM 5% 1/16W 0402; Category : Resistors (Size: 0402); Digikey P/N: 311-4.7KJRCT-ND; Manufacturer: YAGEO; Part Num#: RC0402JR-074K7L; Rating: 1/16W; SolidRun P/N: RE20002; Vol: 5%
R20 = RES1: RES SMD 4.99K OHM 1% 1/16W 0402; Category : Resistors (Size: 0402); Digikey P/N: 311-4.99KLRCT-ND; Manufacturer: YAGEO; Part Num#: RC0402FR-074K99L; Rating: 1/16W; SolidRun P/N: RE20026; Vol: 1%
R105-R108 = RES1: RES SMD 75 OHM 1% 1/16W 0402; Category : Resistors (Size: 0402); Digikey P/N: 311-75.0LRCT-ND; Manufacturer: YAGEO; Part Num#: RC0402FR-0775RL; Rating: 1/16W; SolidRun P/N: RE20401; Vol: 1%
T1 = ATPL-429R: 1000 BASE –T SINGLE PORT PoE MAGNETICS MODULE SMT; # of Mfr: XXX; Category : IC-ETH-POE; Component Eng Status: XXX; Cost: XXX; Excess Inv: XXX; GG Footprint: XXX; IC Input capacitance: n/a; IC TH/smt package/size: N/A; IC family: analog; IC generic number: n/a; IC max Vcc/max input voltage: n/a; IC max output current: n/a; IC power dissipation: n/a; IC speed: n/a; Lead Time (Days): XXX; Leads pitch: N/A; Lifecycle Phase: Prototype; Manufacturer: AOEM; Manufacturer's Part Number: VP6014 LF; Max operating temp: +70; Min operating temp: 0; Mounting Tech: SMT; Number: LT-0548-S0N; Quantity in Stock: XXX; Reflow Soldering Comp: Yes; SolidRun P/N: IC00933; Used In Active Products: Yes; Wave Soldering Comp: No; height: 6; lead count: 24; notes: XXX; Datasheet: http://www.atechoem.com/ProdComSpec/ATPL-429R.pdf
U6 = IC-i210: Intel® Ethernet Controller I210; Category : IC-ETH; Manufacturer: INTEL; Part Num#: WGI210AT S LJXR/1115; SolidRun P/N: IC01191
Y1 = XTAL-4P: FA-128 25.000000MHz 18.0pF +/- 10ppm; Category : OC-CRYSTAL; Digikey P/N: FA-12825.0000MF15Y-C3-ND; Manufacturer: EPSON; Rating: 18pF/10PPM; SolidRun P/N: OC00026; Datasheet: https://support.epson.biz/td/api/doc_check.php?dl=brief_FA-128_en.pdf
C73 = CAP_NP1: CAP CER 22uF ±20% 35V X5R 0805 . Low ESL; Digikey P/N: 445-14428-1-ND; Manufacturer: TDK Corporation; Part Num#: C2012X5R1V226M125AC; Rating: 35V; SolidRun P/N: CA40013; Vol: 20%
C75 = CAP_NP1: CAP CER 0.1uF ±10% 50V X7R 0402; Digikey P/N: 490-10700-1-ND; Manufacturer: Murata Electronics North America; Part Num#: GRM155R71H104KE14D; Rating: 50V; SolidRun P/N: CA20147; Vol: 10%; Voltage: 50V
C100 = CAP_NP1: CAP CER 10uF ±10% 16V X5R 0603; Category: Capacitors (Size: 0603); Digikey P/N: 490-10728-2-ND; Manufacturer: Murata Electronics North America; Part Num#: GRM188R61C106KAALD; Rating: 16V; SolidRun P/N: CA30014; Vol: 10%
C101 = CAP_NP1: CAP CER 0.1uF ±10% 10V X7R 0402; Category: Capacitors (Size: 0402); Digikey P/N: 1276-1002-2-ND; Manufacturer: Samsung Electro-Mechanics; Part Num#: CL05B104KP5NNNC; Rating: 10V; SolidRun P/N: CA20001; Vol: 10%
CON4 = J-FPC40: 40 Position FPC Connector Contacts, Top and Bottom 0.020" (0.50mm) Surface Mount, Right Angle; Digikey P/N: OR729TR-ND; Manufacturer: Omron Electronics Inc-EMC Div; SolidRun P/N: CO00681; Vol: FPC-0.5-T/B; Datasheet: https://media.digikey.com/pdf/Data%20Sheets/Omron%20PDFs/XF2M.pdf
CON7 = J-FPC28-FH41: 28 Position FFC Connector Contacts, Bottom 0.020" (0.50mm) Surface Mount, Right Angle; Category: CON-FPC; Digikey P/N: HFY028TR-ND; Manufacturer: Hirose Electric Co Ltd; SolidRun P/N: CO00730; VOL: FPC-0.5-B; Datasheet: https://www.hirose.com/product/download/?distributor=digikey&type=2d&lang=en&num=FH41-28S-0.5SH(05)
J19 = J-FPC22-HS: FFC & FPC Connectors Bottom 0.5MM 22P HIGH SPEED TRANSMISSION FPC - AV CAMERA; Category : CON-FPC; Digikey P/N: FH55-22S-0.5SH-ND; Manufacturer: HIROSE; SolidRun P/N: CO00677; VOL: FPC-0.5-B-HS; Datasheet: https://www.hirose.com/product/en/products/FH55/FH55-22S-0.5SH/
R43 R45 R47 R49 R52 R53 R56 R59 R119 R141 R142 R144 R147 R155 R169 R172 = RES1: RES SMD 1K OHM 5% 1/16W 0402; Category : Resistors (Size: 0402); Digikey P/N: 311-1.0KJRCT-ND; Manufacturer: YAGEO; Part Num#: RC0402JR-071KL; Rating: 1/16W; SolidRun P/N: RE20010; Vol: 5%
R62 R63 = RES1: RES SMD 100K OHM 1% 1/16W 0402; Category : Resistors (Size: 0402); Digikey P/N: 311-100KLRCT-ND; Manufacturer: YAGEO; Part Num#: RC0402FR-07100KL; Rating: 1/16W; SolidRun P/N: RE20482; Vol: 1%
R66 R112 = RES1: RES SMD 0 OHM JUMPER 1/16W 0402; Digikey P/N: 311-0.0JRCT-ND; Manufacturer: YAGEO; Part Num#: RC0402JR-070RL; Rating: 1/16W; SolidRun P/N: RE20009
R192 R193 = RES1: RES SMD 4.7K OHM 5% 1/16W 0402; Category: Resistors (Size: 0402); Digikey P/N: 311-4.7KJRCT-ND; Manufacturer: YAGEO; Part Num#: RC0402JR-074K7L; Rating: 1/16W; SolidRun P/N: RE20002; Vol: 5%
S3 = SW-DIP-6_SM: DIP Switches/SIP Switches Half Pitch Dip switch 1.6mm height; Category: Switches-DIP; Manufacturer: DIPTRONICS MANUFACTURING; Rating: 0.025A; SolidRun P/N: SW00026; Vol: 24V; Datasheet: http://www.dip.com.tw/en/en-product-information/en-switch002/item/2377-dhnf
U28-U30 = IC-NTSX2102: Voltage Level Translator Bidirectional 1 Circuit 2 Channel 50Mbps 8-XSON, SOT996-2 (2x3); Category: IC-LOGIC; Digikey P/N: 568-12385-2-ND; Manufacturer: NXP USA Inc.; SolidRun P/N: IC01311; VOL: 1.65V-5.5V; Datasheet: https://www.nxp.com/docs/en/data-sheet/NTSX2102.pdf

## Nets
+V0P9A_LAN: C43.1 C49.1 C61.1 C119.1 C120.1 U6.11(VDD0P9) U6.32(VDD0P9) U6.38(VDD0P9_OUT) U6.42(VDD0P90) U6.59(VDD0P9)
+V1P5A_LAN: C33.1 C45.1 C115.1 C117.1 C118.1 U6.39(VDD1P5_OUT) U6.47(VDD1P5) U6.56(VDD1P5)
+V3P3A_LAN: C20.1 C38.1 C60.1 C116.1 L4.2 R18.1 R23.2 R25.1 R26.2 R30.2 R31.2 R33.1 R36.1 R37.1 R38.1 R39.1 U6.10(VDD3P3) U6.27(VDD3P3) U6.41(VDD3P3) U6.51(VDD3P3) U6.64(VDD3P3)
GND: C4.2 C12.2 C13.2 C15.2 C19.2 C20.2 C21.2 C22.2 C23.2 C24.2 C25.2 C26.2 C27.2 C28.2 C29.1 C30.1 C33.2 C34.2 C35.1 C36.1 C37.2 C38.2 C39.2 C42.2 C43.2 C45.2 C49.2 C57.2 C60.2 C61.2 C66.2 C73.2 C75.2 C81.2 C83.2 C84.2 C91.2 C92.2 C95.2 C100.2 C101.2 C115.2 C116.2 C117.2 C118.2 C119.2 C120.2 C137.1 C142.1 C143.1 C144.1 C158.2 C162.2 C163.2 C172.2 CON4.5 CON4.7 CON4.17 CON4.28 CON4.30 CON4.40 CON6.2 CON7.1 CON7.4 CON7.7 CON7.10 CON7.13 CON7.16 CON7.19 CON7.22 CON7.28 CON7.29(G1) CON7.30(G2) CON7.31(G3) CON7.32(G4) CON7.33(G5) CON7.S1 CON7.S2 D4.1 D9.3(GND) D9.8(GND) D9.11(EP1) D9.12(EP2) D9.13(EP3) D10.3(GND) D10.8(GND) D10.11(EP1) D10.12(EP2) D10.13(EP3) D12.1 D15.1 D17.1 D20.1 D21.1 D22.1 D23.11(GND) D24.11(GND) J1.2(TMDS_Data2S) J1.5(TMDS_Data1S) J1.8(TMDS_Data0S) J1.11(TMDS_CLK1S) J1.17(DDC/CEC_GND) J7.5 J7.6 J7.11 J7.17 J7.23 J7.29 J7.35 J7.41 J7.42 J7.48 J7.58 J7.61 J7.64 J7.70 J7.75 J7.76 J9.2 J9.5 J9.8 J9.11 J9.14 J9.17 J9.20 J9.23 J9.26 J9.35 J9.36 J9.70 J9.72 J9.74 J9.76 J9.78 J9.80 J19.10(GND) J19.13(GND) J19.16(GND) J19.19(GND) J19.22(GND) J23.1 J23.4 J5001.7 J5001.8 J5001.10 J5001.13 J5001.16 J5001.19 J5001.22 J5001.25 J5001.30 J5001.33 J5001.36 J5001.42 J5001.47 J5001.52 J5001.57 J5001.58 J5001.63 J5001.64 J5001.69 J5001.70 M2.7(VDC-) M2.10(VDC-) OC1.3(EMITTER) R5.2 R12.2 R17.2 R19.2 R20.2 R24.2 R43.1 R45.1 R47.1 R49.1 R52.1 R53.1 R56.1 R59.1 R62.1 R63.1 R83.2 R87.2 R119.1 R141.1 R142.1 R146.1 R147.1 R149.1 R179.1 R180.1 U2.B1(GND_CH1) U2.B2(GND_CH2) U6.65(EPAD) U12.5(DGND) U12.9(CGND) U12.14(HPOUTFB) U12.22(AGND) U12.33(EPAD) U18.B1(GND_CH1) U18.B2(GND_CH2) U18.B3(GND_CH3) U27.1(GND) U28.4(GND) U29.4(GND) U30.4(GND) Y1.2 Y1.4 ; also on sheet 1 2 3 4 10
GNDC: C4.1 C15.1 C113.2 CON2.SH1(Earth1) CON2.SH2(Earth2) J1.S1 J1.S2 J1.S3 J1.S4 J3.13(SH1) J3.14(SH2) J16.1 J17.1 J21.1 J22.1 ; also on sheet 1 4 10
VDD_1V8: C81.1 C83.1 C163.1 C172.1 R192.1 R193.1 R200.1 R201.1 U12.6(DCVDD) U12.7(CPVDD) U12.23(AVDD) U27.2(Vout) U28.8(VCCB) U29.8(VCCB) U30.8(VCCB)
VDD_3V3: C84.1 C95.1 C158.1 CON2.13 D7.A(ANODE) J3.10 J3.12 L4.1 R34.1 R35.1 R44.1 R46.1 R48.1 R50.1 R51.1 R54.1 R55.1 R58.1 R60.1 R70.1 R112.2 R129.1 R130.1 R143.1 R144.1 R148.1 R155.1 R169.1 R172.1 R190.1 SH1.2 U12.4(DBVDD) U12.19(MICVDD) U27.3(Vin) U28.1(VCCA) U28.5(OE) U29.1(VCCA) U29.5(OE) U30.1(VCCA) U30.5(OE) ; also on sheet 2 3 4 10
VIN: R66.2 ; also on sheet 1
VIN+: D25.3(DC_OUT_PLUS) D26.3(DC_OUT_PLUS) D27.2(Cathod) L10.1 SH2.1
VIN-: D25.4(DC_OUT_MINUS) D26.4(DC_OUT_MINUS) D27.1(Anode) L11.1 SH3.1
ADJ: J23.3 M2.9(ADJ) R12.1
AT-DET: J24.3 M2.3(AT-DET) OC1.2(CATHODE)
AUD_nMUTE: J9.39 J9.55
BOOT_MODE0: J5001.3 R62.2 R64.1 S3.2(A2)
BOOT_MODE1: J5001.5 R61.1 R63.2 S3.1(A1)
C_MDI_TRXN0: J3.2 T1.22
C_MDI_TRXN1: J3.6 T1.19
C_MDI_TRXN2: J3.5 T1.16
C_MDI_TRXN3: J3.8 T1.13
C_MDI_TRXP0: J3.1 T1.23
C_MDI_TRXP1: J3.3 T1.20
C_MDI_TRXP2: J3.4 T1.17
C_MDI_TRXP3: J3.7 T1.14
CLK_25M: CON4.33 J9.57
CLKO2: J7.38 U30.2(A1)
CLKO_25MHz: C57.1 J9.41 R35.2 U6.17(PE_RST_N)
CSI_P1_CKN: CON7.9 J5001.61
CSI_P1_CKP: CON7.8 J5001.59
CSI_P1_DN0: CON7.15 J5001.54
CSI_P1_DN1: CON7.12 J5001.68
CSI_P1_DN2: CON7.6 J5001.62
CSI_P1_DN3: CON7.3 J5001.67
CSI_P1_DP0: CON7.14 J5001.56
CSI_P1_DP1: CON7.11 J5001.66
CSI_P1_DP2: CON7.5 J5001.60
CSI_P1_DP3: CON7.2 J5001.65
CT_PWP: C29.2 C30.2 C35.2 C36.2 CON2.P2
CT_PWP0: C137.2 T1.10
CT_PWP1: C142.2 T1.7
CT_PWP2: C143.2 T1.4
CT_PWP3: C144.2 T1.1
DCDC_5V: C12.1 C13.1 C100.1 C101.1 CON7.25 CON7.26 CON7.27 F1.1 J9.71 J9.73 J9.75 J9.77 J9.79 J19.1(VCC5) J19.4(5V) J19.7(5V) ; also on sheet 1 2 4 10
DCDC_5V_CN: D2.C(CATHODE) D4.2 J1.18(5V) R7.2 R95.1 R96.1
DSI_CKN: J5001.11 R76.1 R160.1
DSI_CKP: J5001.9 R75.1 R159.1
DSI_DN0: J5001.12 R80.1 R161.1
DSI_DN1: J5001.21 R73.1 R164.1
DSI_DN2: J5001.15 R71.1 R166.1
DSI_DN3: J5001.4 R78.1 R167.1
DSI_DP0: J5001.14 R79.1 R162.1
DSI_DP1: J5001.23 R74.1 R163.1
DSI_DP2: J5001.17 R72.1 R165.1
DSI_DP3: J5001.6 R77.1 R168.1
DSI_EN: J9.34 U30.3(A2) ; also on sheet 10
DSI_TS_nINT: J19.2(GPIO0) J5001.43 ; also on sheet 10
DSIC_CKN: J19.14(CSI2-TXC_N) R160.2
DSIC_CKP: J19.15(CSI2-TXC_P) R159.2
DSIC_DN0: J19.20(CSI2-TXD0_N) R161.2
DSIC_DN1: J19.17(CSI2-TXD1_N) R164.2
DSIC_DN2: J19.11(CSI2-TXD2_N) R166.2
DSIC_DN3: J19.8(CSI_TXD3_N) R167.2
DSIC_DP0: J19.21(CSI2-TXD0_P) R162.2
DSIC_DP1: J19.18(CSI2-TXD1_P) R163.2
DSIC_DP2: J19.12(CSI2-TXD2_P) R165.2
DSIC_DP3: J19.9(CSI2-TXD3_P) R168.2
ECSPI2_MISO: J9.45 ; also on sheet 2
ECSPI2_MOSI: J9.47 ; also on sheet 2
ECSPI2_SCLK: J9.49 ; also on sheet 2
ECSPI2_SS0: J9.32 ; also on sheet 2
FLASH_1V8: CON7.23 U28.7(B1)
FLASH_3V3: TP5.1(TP) U28.2(A1)
FREX_1V8: CON7.18 U30.6(B2)
GPIO1: J7.44 ; also on sheet 2
GPIO_1V8: CON7.17 U28.6(B2)
GPIO_3V3: TP6.1(TP) U28.3(A2)
HDMI_AUXN: C175.1 J7.79
HDMI_AUXN_C: C175.2 U18.A1(CH1_IN+)
HDMI_AUXP: C174.1 J7.77
HDMI_AUXP_C: C174.2 U18.A2(CH1_IN-)
HDMI_CEC: D22.2 J1.13(CEC) J7.43 R97.2
HDMI_CLKN: J7.39 U18.A3(CH2_IN+)
HDMI_CLKN_CN: J1.12(TMDS_CLK1-) U18.C3(CH2_OUT+)
HDMI_CLKP: J7.37 U18.A4(CH2_IN-)
HDMI_CLKP_CN: J1.10(TMDS_CLK1+) U18.C4(CH2_OUT-)
HDMI_DDC_SCL: D21.2 J1.15(SCL) J7.45 R96.2
HDMI_DDC_SDA: D20.2 J1.16(SDA) J7.47 R95.2
HDMI_HPD: J1.19(HPD) J7.49 R5.1 U18.C1(CH1_OUT+)
HDMI_TXN0: J7.33 U18.A5(CH3_IN+)
HDMI_TXN0_CN: J1.9(TMDS_Data0-) U18.C5(CH3_OUT+)
HDMI_TXN1: J7.27 U2.C4(CH2_OUT-)
HDMI_TXN1_CN: J1.6(TMDS_Data1-) U2.A4(CH2_IN-)
HDMI_TXN2: J7.21 U2.C2(CH1_OUT-)
HDMI_TXN2_CN: J1.3(TMDS_Data2-) U2.A2(CH1_IN-)
HDMI_TXP0: J7.31 U18.A6(CH3_IN-)
HDMI_TXP0_CN: J1.7(TMDS_Data0+) U18.C6(CH3_OUT-)
HDMI_TXP1: J7.25 U2.C3(CH2_OUT+)
HDMI_TXP1_CN: J1.4(TMDS_Data1+) U2.A3(CH2_IN+)
HDMI_TXP2: J7.19 U2.C1(CH1_OUT+)
HDMI_TXP2_CN: J1.1(TMDS_Data2+) U2.A1(CH1_IN+)
HDMI_Utility/HEAC+_CN: J1.14(Reserve) U18.C2(CH1_OUT-)
I2C2_SCL: J9.53 U12.2(SCLK) ; also on sheet 4
I2C2_SDA: J9.51 U12.3(SDA) ; also on sheet 4
I2C3_SCL: CON4.37 J9.31 J19.3(I2C_SCL) U6.34(SMB_CLK) U29.2(A1) ; also on sheet 2 3 10
I2C3_SCL_1V8: CON7.20 R193.2 U29.7(B1)
I2C3_SDA: CON4.38 J9.33 J19.5(I2C_SDA) U6.36(SMB_DATA) U29.3(A2) ; also on sheet 2 3 10
I2C3_SDA_1V8: CON7.21 R192.2 U29.6(B2)
LED_10_100_LED_1000: J9.25 R101.2
LED_ACT: J9.27 R8.2
M.2_GPS_EN#: J9.28 ; also on sheet 3
M.2_PCIe_3V3_EN: J7.18 ; also on sheet 1
M.2_RESET#: J7.13 ; also on sheet 3
M.2_W_DIS#: J5001.24 ; also on sheet 3
M.2_WAKW_ON_LAN: J5001.27 ; also on sheet 3
MDI_TRXN0: D9.4(IN3) D9.7(OUT3) J9.19 T1.3
MDI_TRXN1: D9.1(IN1) D9.10(OUT1) J9.13 T1.6
MDI_TRXN2: D10.4(IN3) D10.7(OUT3) J9.7 T1.9
MDI_TRXN3: D10.1(IN1) D10.10(OUT1) J9.1 T1.12
MDI_TRXP0: D9.5(IN4) D9.6(OUT4) J9.21 T1.2
MDI_TRXP1: D9.2(IN2) D9.9(OUT2) J9.15 T1.5
MDI_TRXP2: D10.5(IN4) D10.6(OUT4) J9.9 T1.8
MDI_TRXP3: D10.2(IN2) D10.9(OUT2) J9.3 T1.11
MDSI_CKN: R76.2 ; also on sheet 10
MDSI_CKP: R75.2 ; also on sheet 10
MDSI_DN0: R80.2 ; also on sheet 10
MDSI_DN1: R73.2 ; also on sheet 10
MDSI_DN2: R71.2 ; also on sheet 10
MDSI_DN3: R78.2 ; also on sheet 10
MDSI_DP0: R79.2 ; also on sheet 10
MDSI_DP1: R74.2 ; also on sheet 10
MDSI_DP2: R72.2 ; also on sheet 10
MDSI_DP3: R77.2 ; also on sheet 10
MIBIAS: R92.1 U12.20(MICBIAS)
MICIN: C157.1 L8.1 R92.2
Mini-PCIe_PREST#: J7.10 ; also on sheet 3
Mini-PCIe_W_DIS#: J5001.26 ; also on sheet 3
NVCC_SD2: J9.61 ; also on sheet 2
nWDOG: J7.32 TP3.1(TP)
ONOFF: J9.62 ; also on sheet 2
P0_Led0: R2.1 U6.33(LED2)
P0_Led1: R1.1 U6.31(LED0)
P0_Led2: CON2.11 U6.30(LED1)
P0_MDIN0: C22.1 CON2.P10 D24.3(IN/OUT3) U6.57(MDI_0_N)
P0_MDIN1: C24.1 CON2.P8 D24.9(IN/OUT6) U6.54(MDI_1_N)
P0_MDIN2: C26.1 CON2.P6 D23.3(IN/OUT3) U6.52(MDI_2_N)
P0_MDIN3: C28.1 CON2.P4 D23.9(IN/OUT6) U6.49(MDI_3_N)
P0_MDIP0: C21.1 CON2.P9 D24.1(IN/OUT1) U6.58(MDI_0_P)
P0_MDIP1: C23.1 CON2.P7 D24.7(IN/OUT4) U6.55(MDI_1_P)
P0_MDIP2: C25.1 CON2.P5 D23.1(IN/OUT1) U6.53(MDI_2_P)
P0_MDIP3: C27.1 CON2.P3 D23.7(IN/OUT4) U6.50(MDI_3_P)
PCIE1_REF_CLKN_CN: J5001.20 ; also on sheet 3
PCIE1_REF_CLKP_CN: J5001.18 ; also on sheet 3
PCIE1_RXN_C: J5001.40 ; also on sheet 3
PCIE1_RXP_C: J5001.38 ; also on sheet 3
PCIE1_TXN_C: J5001.34 ; also on sheet 3
PCIE1_TXP_C: J5001.32 ; also on sheet 3
PCIE2_REF_CLKN_CN: J7.3 U6.25(PE_CLKN)
PCIE2_REF_CLKP_CN: J7.1 U6.26(PE_CLKP)
PCIE2_RXN: C58.2 J7.2
PCIE2_RXP: C59.2 J7.4
PCIE2_TXN: J7.7 U6.23(PE_RN)
PCIE2_TXP: J7.9 U6.24(PE_RP)
PMIC_ON: J5001.1 TP4.1(TP)
POE_AT_DET: J7.14 OC1.4(COLLECTOR) R190.2
POE_VIN+: C67.1 J24.1 L14.2 M2.1(VIN+) OC1.1(ANODE) SH2.2
POE_VIN-: C66.1 J24.2 L15.2 M2.2(VIN-) SH3.2
POE_VIN_12V: C19.1 C37.1 C42.1 C67.2 J23.2 M2.8(VDC+) ; also on sheet 1
Power Data+: D26.1(AC_IN) R107.1 T1.21
Power Data-: D26.2(AC_IN) R108.1 T1.24
Power Spare+: D25.1(AC_IN) R105.1 T1.15
Power Spare-: D25.2(AC_IN) R106.1 T1.18
PPS: CON4.34 J9.29
PWM2_OUT: J9.68 ; also on sheet 2
RTC_CLKO: J7.15 ; also on sheet 3
SAI1_MCLK: CON4.4 J7.36
SAI1_RXC: CON4.18 J7.69
SAI1_RXD0: CON4.20 J7.78 R46.2 R47.2
SAI1_RXD1: CON4.21 J7.80 R44.2 R45.2
SAI1_RXD2: CON4.22 J7.72 R49.2 R51.2
SAI1_RXD3: CON4.23 J7.74 R50.2 R52.2
SAI1_RXD4: CON4.24 J7.67 R130.2 R141.2
SAI1_RXD5: CON4.25 J7.50 R147.2 R148.2
SAI1_RXD6: CON4.26 J7.63 R119.2 R129.2
SAI1_RXD7: CON4.27 J7.46 R54.2 R56.2
SAI1_RXFS: CON4.19 J7.71
SAI1_TXC: CON4.6 J7.12
SAI1_TXD0: CON4.9 J7.22 R59.2 R60.2
SAI1_TXD1: CON4.10 J7.24 R53.2 R55.2
SAI1_TXD2: CON4.11 J5001.41 R170.2 R179.2 S3.3(A3)
SAI1_TXD3: CON4.12 J7.28 R142.2 R143.2
SAI1_TXD4: CON4.13 J5001.51 R171.2 R180.2 S3.4(A4)
SAI1_TXD5: CON4.14 J9.54 R149.2 R150.2 S3.5(A5)
SAI1_TXD6: CON4.15 J9.64 R145.2 R146.2 S3.6
SAI1_TXD7: CON4.16 J7.20 R43.2 R48.2
SAI1_TXFS: CON4.8 J7.30
SAI2_MCLK: J7.59 R69.1
SAI2_RXD: J7.57 U12.31(ADCDAT) ; also on sheet 2
SAI2_TXC: J7.51 R68.1
SAI2_TXD: J7.53 U12.32(DACDAT)
SAI2_TXFS: J7.55 U12.30(LRCLK)
SAI3_MCLK: CON4.29 J7.8
SD2_CLK: J9.38 ; also on sheet 2
SD2_CMD: J9.40 ; also on sheet 2
SD2_DATA0: J9.42 ; also on sheet 2
SD2_DATA1: J9.44 ; also on sheet 2
SD2_DATA2: J9.46 ; also on sheet 2
SD2_DATA3: J9.48 ; also on sheet 2
SD2_nCD: J9.50 ; also on sheet 2
SD2_VSELECT: J7.73 ; also on sheet 2
SPDIF_TX: J7.16 J19.6(GPIO3) ; also on sheet 10
STROBE_1V8: CON7.24 U30.7(B1)
SWDIO1: J9.30 J9.59
SYS_nRST: J7.65 ; also on sheet 2
TERMINAL_RX: J7.54 ; also on sheet 2
TERMINAL_TX: J7.52 ; also on sheet 2
UART2_CTS: J5001.48 ; also on sheet 2
UART2_RTS: J5001.50 ; also on sheet 2
UART2_RXD: J5001.44 ; also on sheet 2
UART2_TXD: J5001.46 ; also on sheet 2
UART3_CTS: J5001.37 ; also on sheet 2
UART3_RTS: J5001.39 ; also on sheet 2
UART3_RXD: J5001.31 ; also on sheet 2
UART3_TXD: J5001.29 ; also on sheet 2
USB1_DN: J9.18 ; also on sheet 4
USB1_DP: J9.16 ; also on sheet 4
USB1_PWR_EN: J5001.28 ; also on sheet 4
USB1_RXN: J9.12 ; also on sheet 4
USB1_RXP: J9.10 ; also on sheet 4
USB1_TXN: J9.6 ; also on sheet 4
USB1_TXP: J9.4 ; also on sheet 4
USB1_VBUS: J9.43 ; also on sheet 4
USB2_DN: J9.24 ; also on sheet 4
USB2_DP: J9.22 ; also on sheet 4
USB2_RXN: J7.62 ; also on sheet 4
USB2_RXP: J7.60 ; also on sheet 4
USB2_TXN: J7.66 ; also on sheet 4
USB2_TXP: J7.68 ; also on sheet 4
USB2_VBUS: J9.52 ; also on sheet 4
USB-HUB_RST#: J7.26 ; also on sheet 4
USB_HUB_CH1_PWR_EN: J9.37 ; also on sheet 4
WIFI_DN: J5001.55 ; also on sheet 4
WIFI_DP: J5001.53 ; also on sheet 4
N403526: J3.11 R101.1
N403568: C113.1 C121.2 C122.2 C123.2 C124.2
N404040: J3.9 R8.1
N408710: C59.1 U6.21(PE_TP)
N408772: C58.1 U6.20(PE_TN)
N408866: C34.1 R28.1 Y1.3
N408896: C39.1 R27.1 Y1.1
N457692: R144.2 R145.1 S3.7(B6)
N457696: R150.1 R155.2 S3.8(B5)
N457700: R171.1 R172.2 S3.9(B4)
N457708: R169.2 R170.1 S3.10(B3)
N564536: C121.1 R105.2
N564551: C122.1 R106.2
N564572: C123.1 R107.2
N564589: C124.1 R108.2
N599639: R28.2 U6.46(XTAL1)
N599643: R27.2 U6.45(XTAL2)
N599704: R20.1 U6.48(RSET)
N600152: C44.1 U6.40(CTOP)
N600165: C44.2 U6.37(CBOT)
N600600: R34.2 U6.16(PE_WAKE_N)
N603649: R33.2 U6.14(NVM_SO)
N604312: R37.2 U6.19(JTAG_CLK)
N604319: R39.2 U6.29(JTAG_TDI)
N604326: R25.2 U6.4(JTAG_TDO)
N604333: R36.2 U6.18(JTAG_TMS)
N604340: R38.2 U6.28(DEV_OFF_N)
N604353: R18.2 U6.1(LAN_PWR_GOOD)
N604561: R23.1 U6.5(NC_SI_RXD1)
N604565: R26.1 U6.6(NC_SI_RXD0)
N604569: R31.1 U6.8(NC_SI_TXD1)
N604573: R30.1 U6.9(NC_SI_TXD0)
N604655: R24.1 U6.7(NC_SI_TX_EN)
N604659: R17.1 U6.3(NC_SI_CRS_DV)
N604669: R19.1 U6.2(NC_SI_CLK_IN)
N617074: L10.2 L12.1
N617574: L11.2 L13.1
N617578: L13.2 L15.1
N658097: CON6.1 D17.2 L8.2
N949333: CON2.12 R2.2
N949648: CON2.14 R1.2
N1176725: J9.63 J9.65 J9.67 J9.69 SH1.1
N1280503: C93.1 CON6.4 D15.2 U12.13(HPOUTL)
N1280510: C94.1 CON6.3 D12.2 U12.15(HPOUTR)
N1280657: R69.2 U12.28(MCLK)
N1280673: R68.2 U12.29(GPIO4/BCLK)
N1280912: C92.1 U12.12(CPVOUTN)
N1280919: C91.1 U12.11(CPVOUTP)
N1280926: C90.1 U12.8(CPCA)
N1280930: C90.2 U12.10(CPCB)
N1280942: C94.2 R83.1
N1280946: C93.2 R87.1
N1283591: C162.1 U12.21(VMIDC)
N1283735: C157.2 U12.24(IN2R)
N3214170: L12.2 L14.1
N4099773: R64.2 R70.2 R200.2 S3.12(B1)
N4099777: R58.2 R61.2 R201.2 S3.11(B2)
N17018633: C73.1 C75.1 CON4.1 CON4.2 CON4.3 R66.1
N17018968: CON4.39 R112.1
N100828512: D2.A(ANODE) F1.2 R7.1
N104602033: D7.C(CATHODE) R97.1

Not connected (* = marked no-connect by the designer): CON2 P1; CON4 31 32 35 36; CON6 5 6; D23 2(NC1)* 4(NC2)* 5(3.3V/N.C.)* 8(NC3)* 10(NC4)*; D24 2(NC1)* 4(NC2)* 5(3.3V/N.C.)* 8(NC3)* 10(NC4)*; J7 34 40 56; J9 56 58 60 66; J11 1; J12 1; J13 1; J24 4* 5* 6*; J5001 2 35 45 49; M2 4(NC1)* 5(NC2)* 6(NC3)*; U6 12(NVM_SI) 13(NVM_SK) 15(NVM_CS_N) 22(RSVD_22_G) 35(SMB_ALRT_N) 43(NC_SI_ARB_IN) 44(NC_SI_ARB_OUT) 60(SDP3) 61(SDP1/PCIE_DIS) 62(SDP2) 63(SDP0); U12 1(GPIO1/IRQ)* 16(LINEOUTL)* 17(LINEOUTFB)* 18(LINEOUTR)* 25(IN1R/DMICDAT2)* 26(IN2L)* 27(IN1L/DMICDAT1)*

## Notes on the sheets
sheet 5
- HDMI TYPEA
- HDMI_D2P
- HDMI_D2N
- HDMI_D1P
- HDMI_D0P
- HDMI_D1N
- HDMI_D0N
- HDMI_CLKP
- HDMI_CEC
- HDMI_CLKN
- HDMI_DDC_SCL
- HDMI_DDC_SDA
- HDMI_5V
- HPD
sheet 6
- Audio DAC
- HP JACK 3.5mm
- HSL
- GND
- HSR
- MIC
- 3.5mm POLE
- CTIA standard
- HSL
- HSR
- GND
- MIC
sheet 7
- PD 10K TO GND
- PD 10K TO GND
- CPU-AT-DET
- PU 10K TO 3V3 LAN
- PD 10K TO GND
- I2C 100KHz
- PU 10K TO 3V3 LAN
- PU 10K TO 3V3 LAN
- PU 10K TO 3V3 LAN
- PU 10K TO 3V3 LAN
- PU 10K TO 3V3 LAN
- PU 10K TO 3V3 LAN
- PU 10K TO 3V3 LAN
- PU 10K TO 3V3 LAN
- PU 3.3K TO 3V3 LAN
- PU 3.3K TO 3V3 LAN
- PU 3.3K TO 3V3 LAN
sheet 8
- SAI3_RXC
- SAI3_RXFS
- BT_CFG15
- BT_CFG8
- BT_CFG9
- BT_CFG11
- BT_CFG7
- BT_CFG10
- BT_CFG5
- BT_CFG12
- USB1_ID
- BT_CFG6
- BT_CFG4
- BT_CFG2
- BT_CFG3
- BT_CFG0
- BT_CFG1
- BT_CFG10
- BT_CFG12
- BT_CFG13
- 1
- J5001
- BT_CFG13
- NEW, Enables flashing the BT from carrier
- BT_CFG14
- NEW
- NEW, Enables flashing the BT from carrier
- J7
- 1
- BT_CFG14
- 1
- J9
- PIN -> 0.3A
- SR-uSOM-mx6
- SR-uSOM-mx6
- SR-uSOM-mx6
- MECH_X_Y is a mechanical hole that the hole size is X mm and padstack is Y mm.
  J15, J16 and J17 are M2.5
  J18, J19 and J27 are M1.8
  J27 is a new mechanical hol for MicroSOM rev 1.4 and newer
sheet 9
- EXP CN
- XF2M-4015-1AH
- BASLER
